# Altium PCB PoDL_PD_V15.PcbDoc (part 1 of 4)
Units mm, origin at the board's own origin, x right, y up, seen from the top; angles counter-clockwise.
Board outline 145 x 75 mm, 4 copper layers (Top Layer, Signal Layer 2, Signal Layer 3, Bottom Layer), stack 1.586 mm thick; 346 components, 228 nets, 1035 pads, 619 vias.
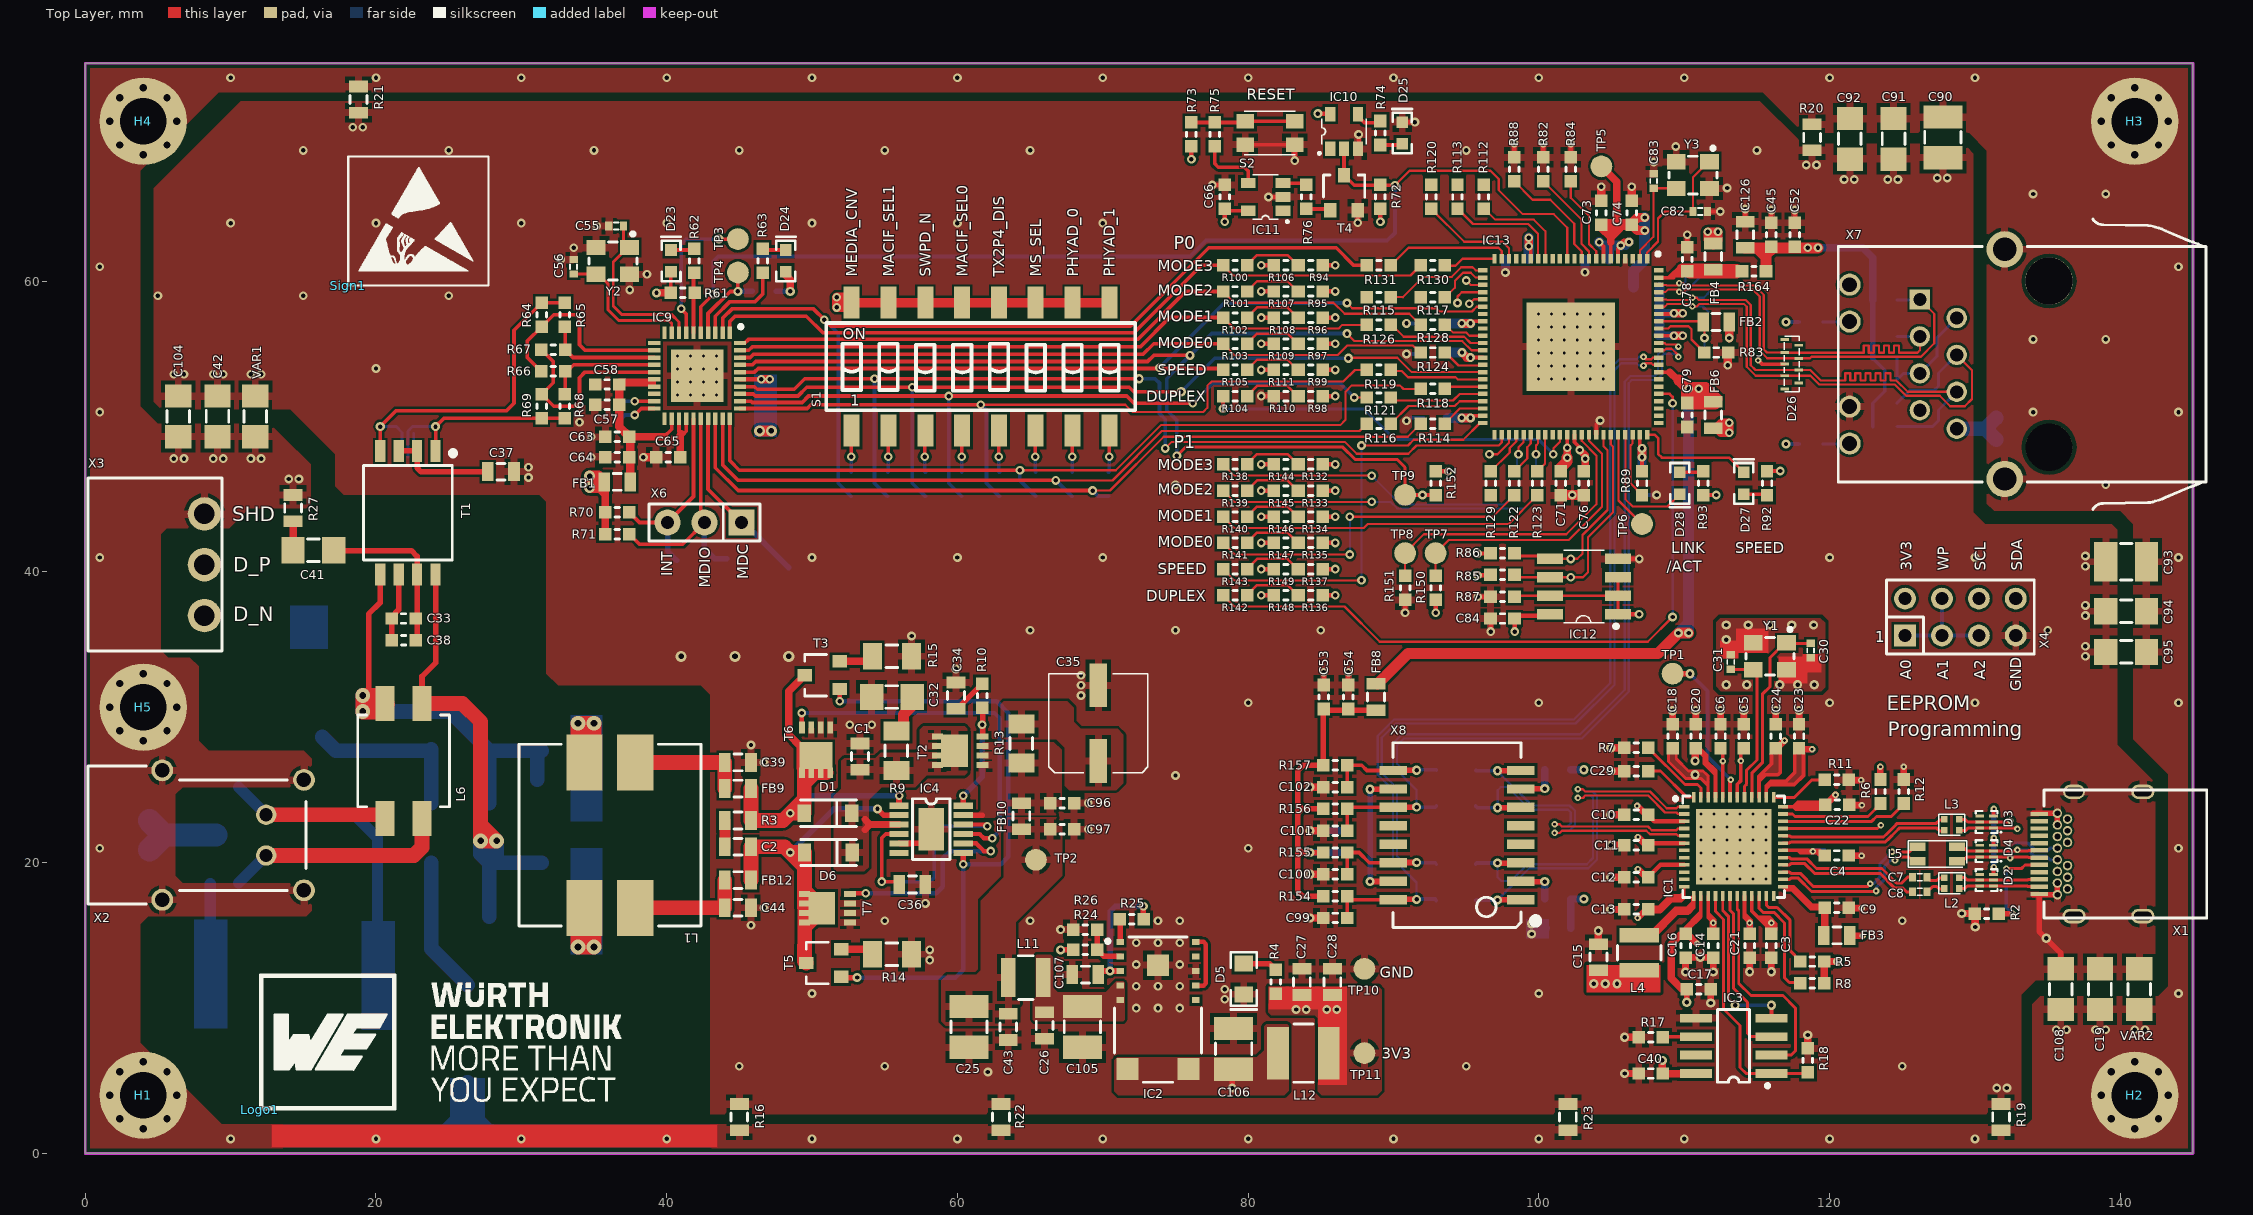
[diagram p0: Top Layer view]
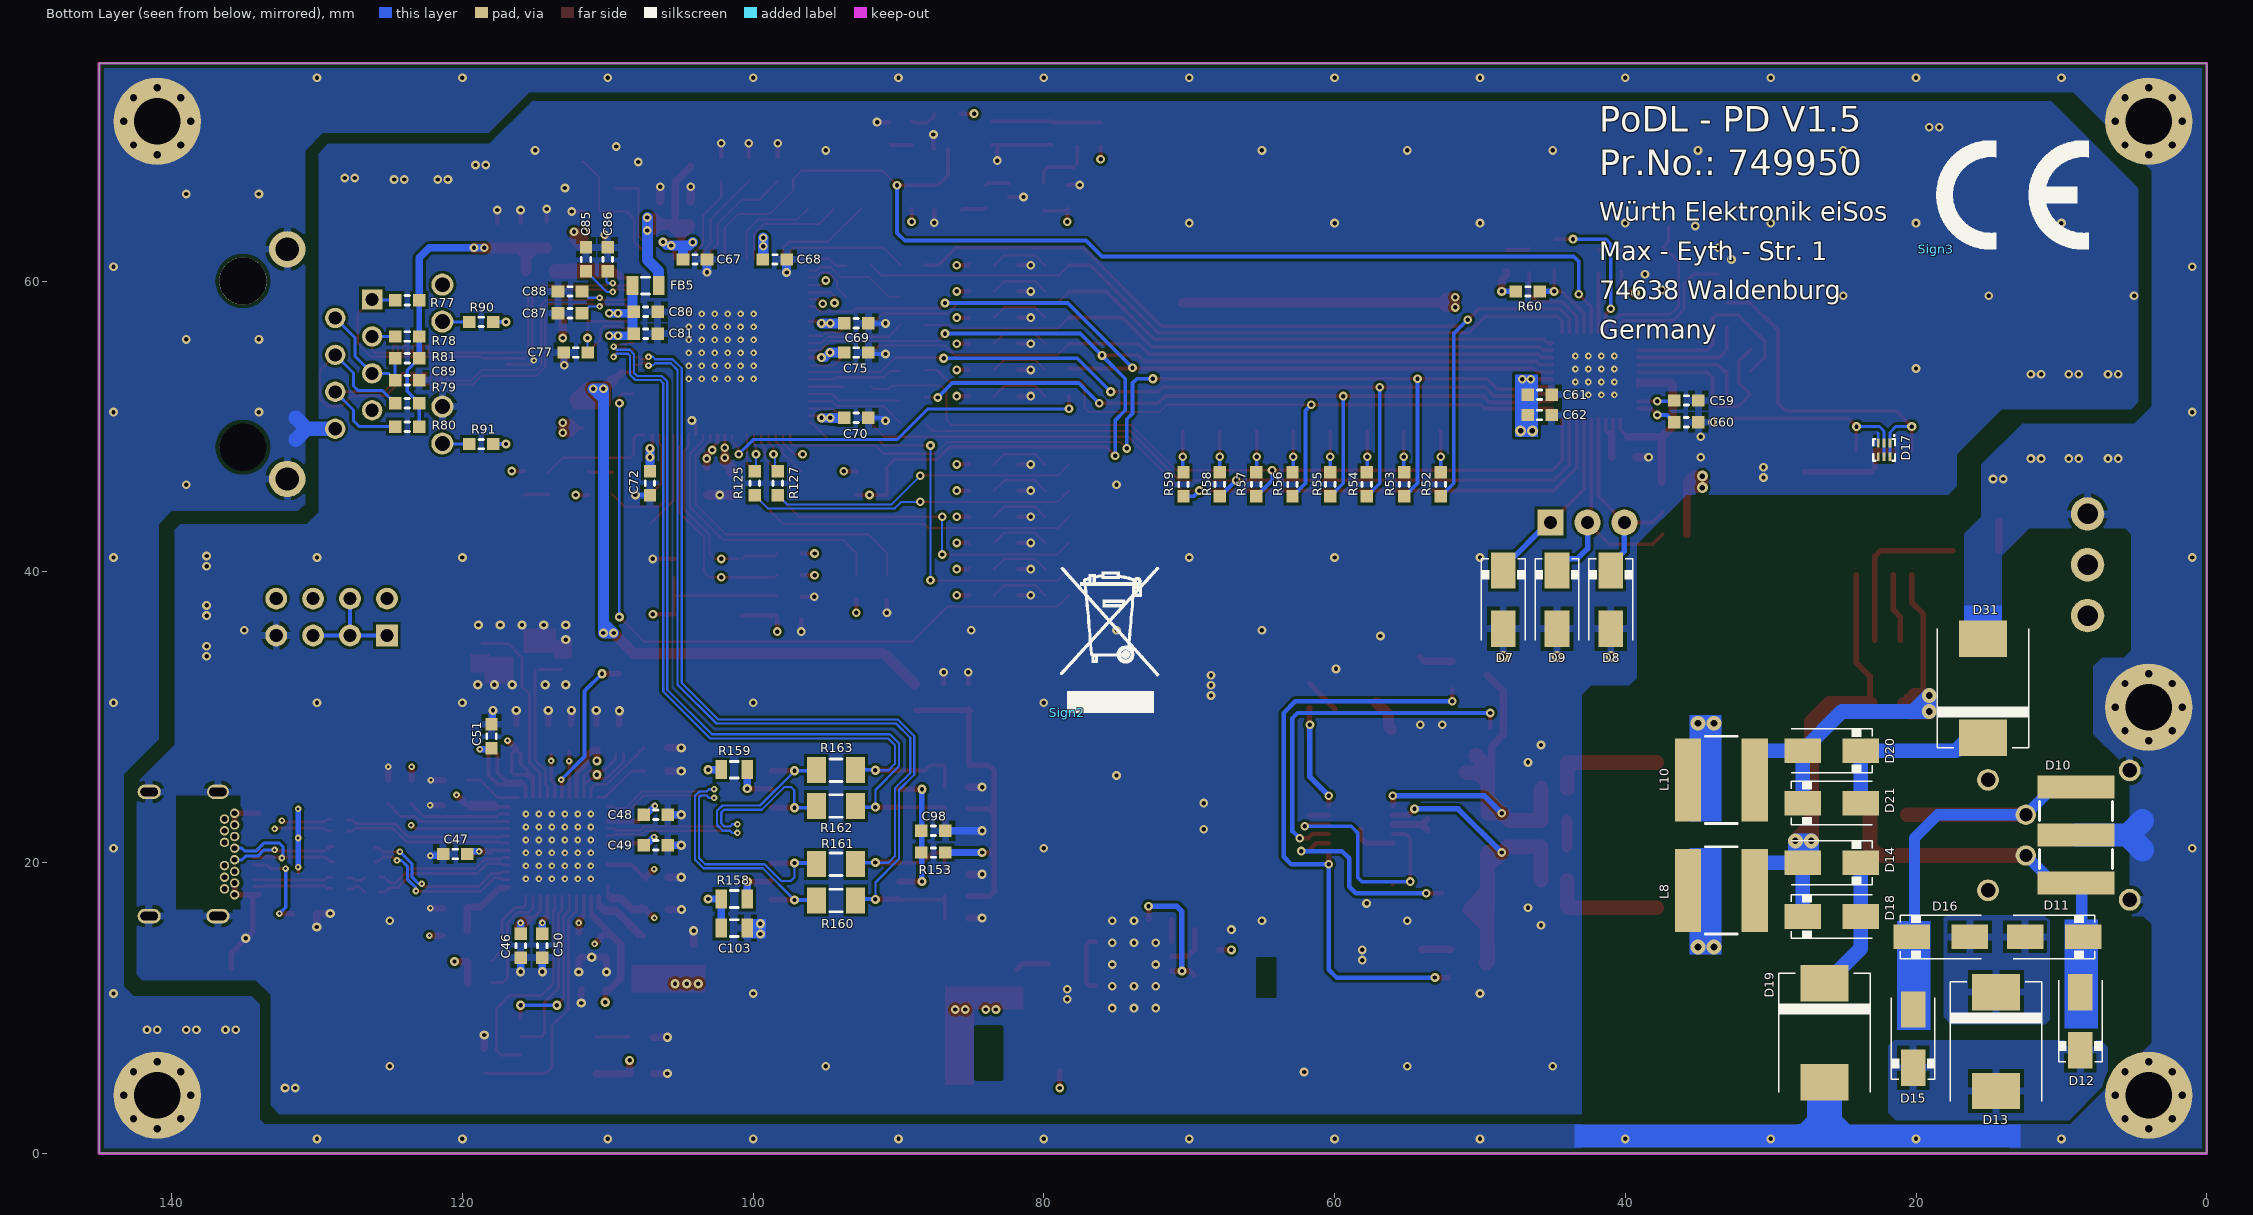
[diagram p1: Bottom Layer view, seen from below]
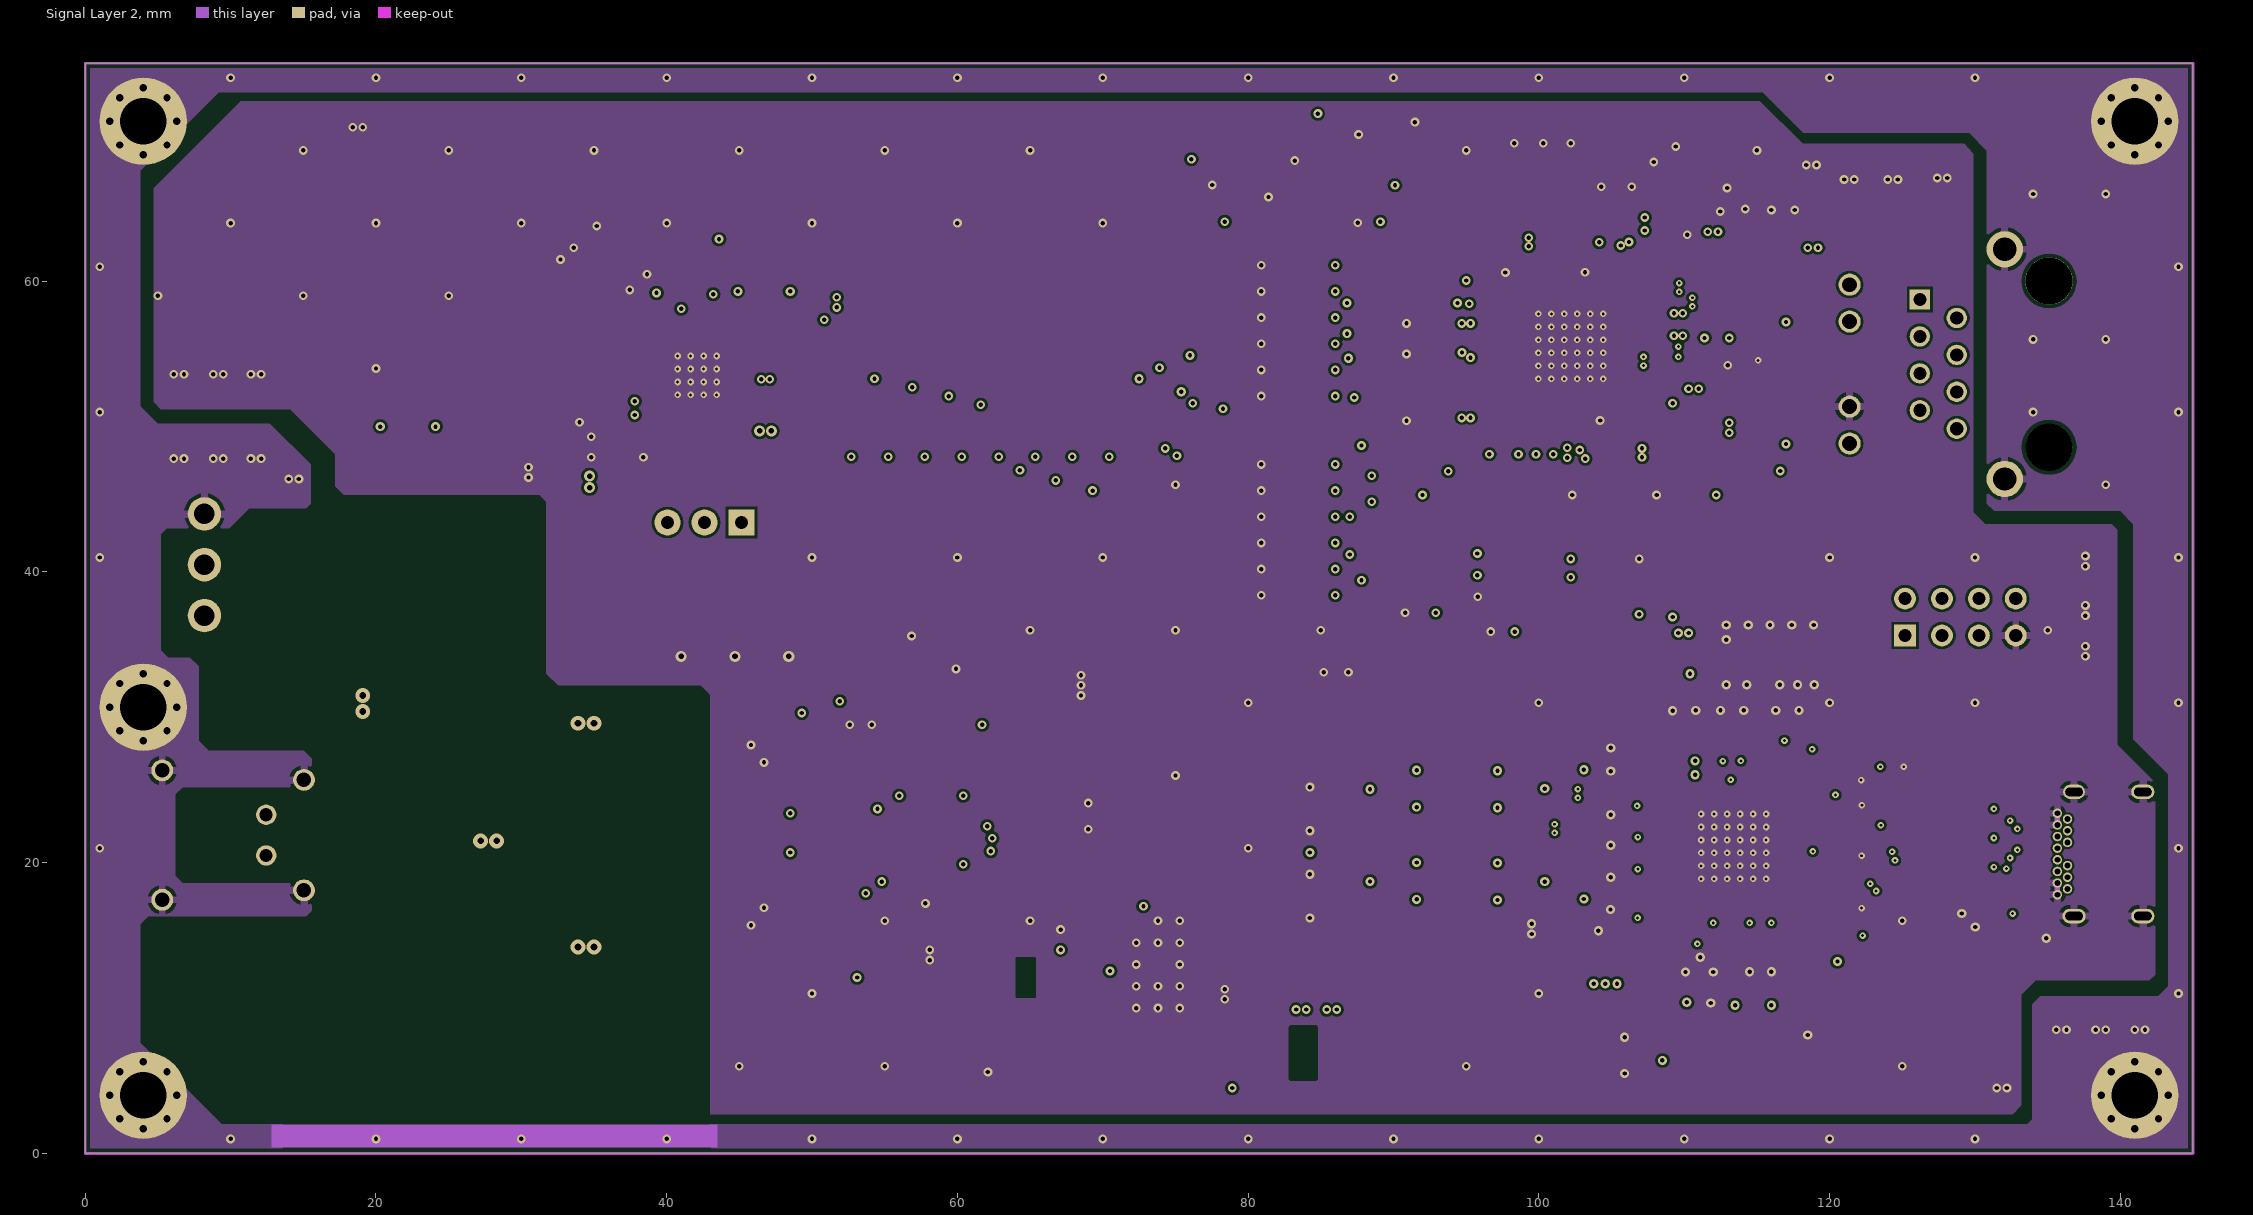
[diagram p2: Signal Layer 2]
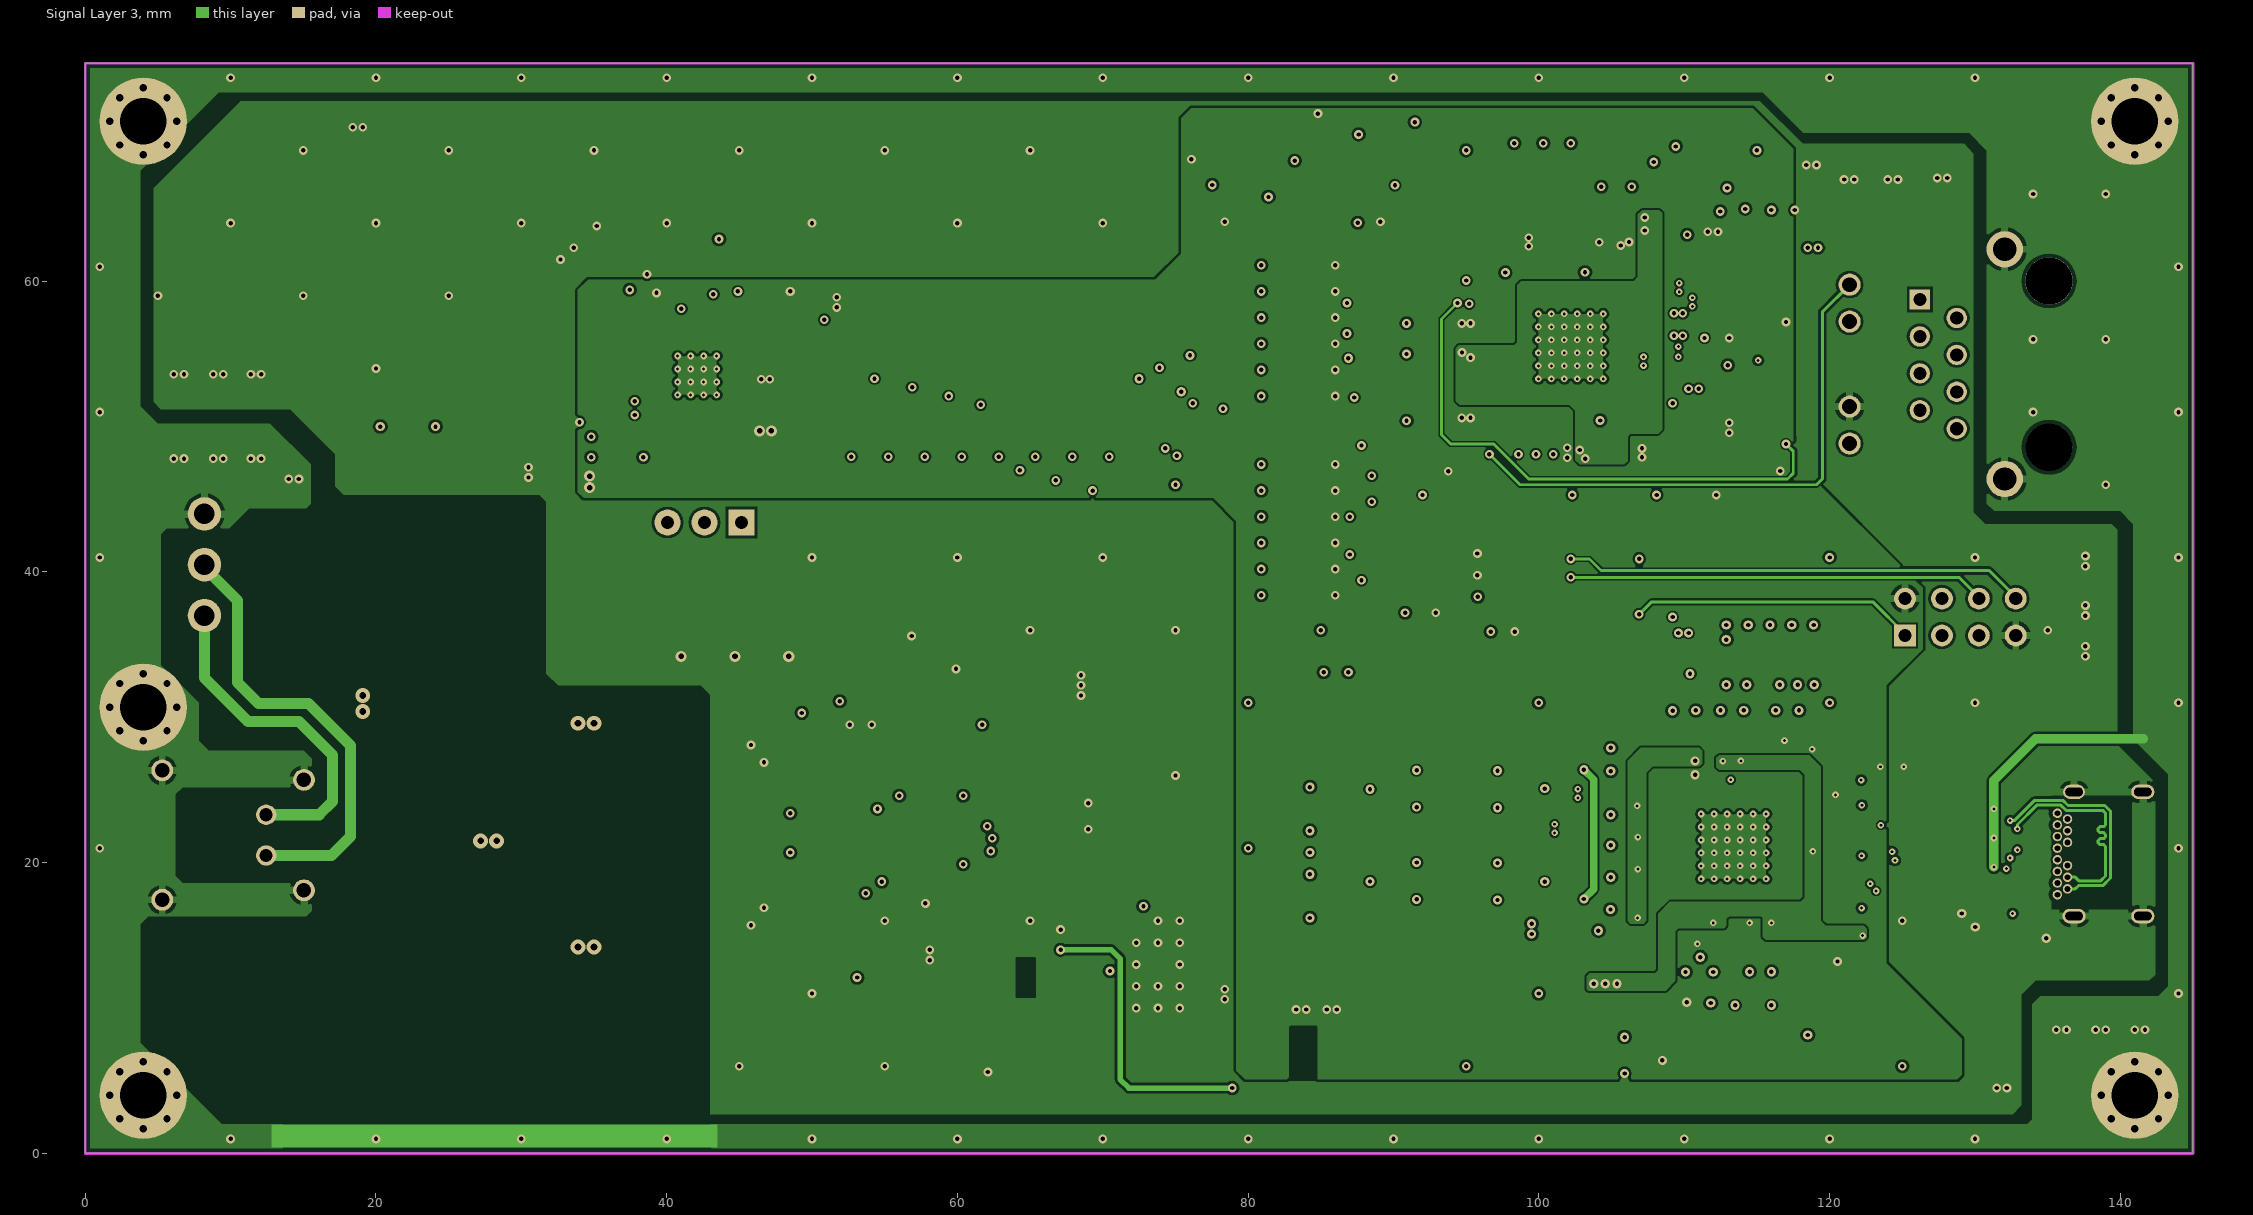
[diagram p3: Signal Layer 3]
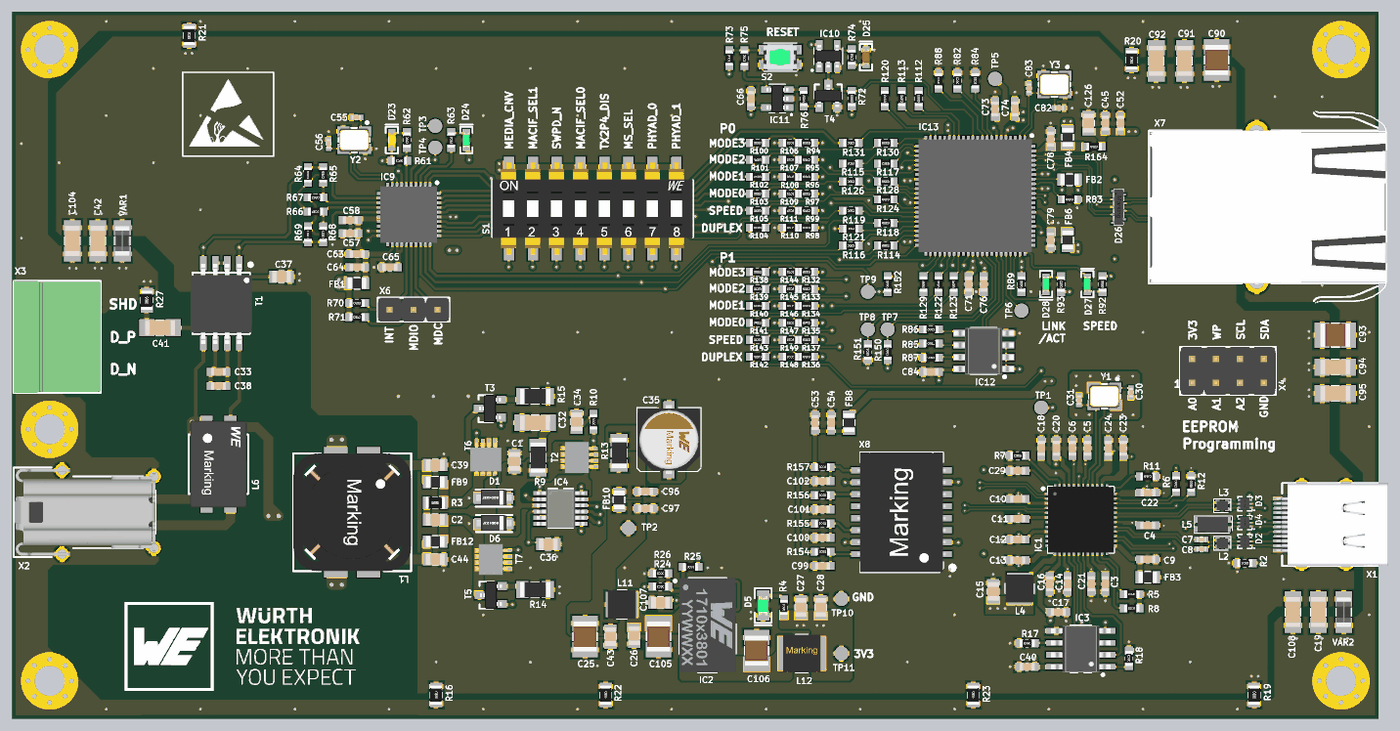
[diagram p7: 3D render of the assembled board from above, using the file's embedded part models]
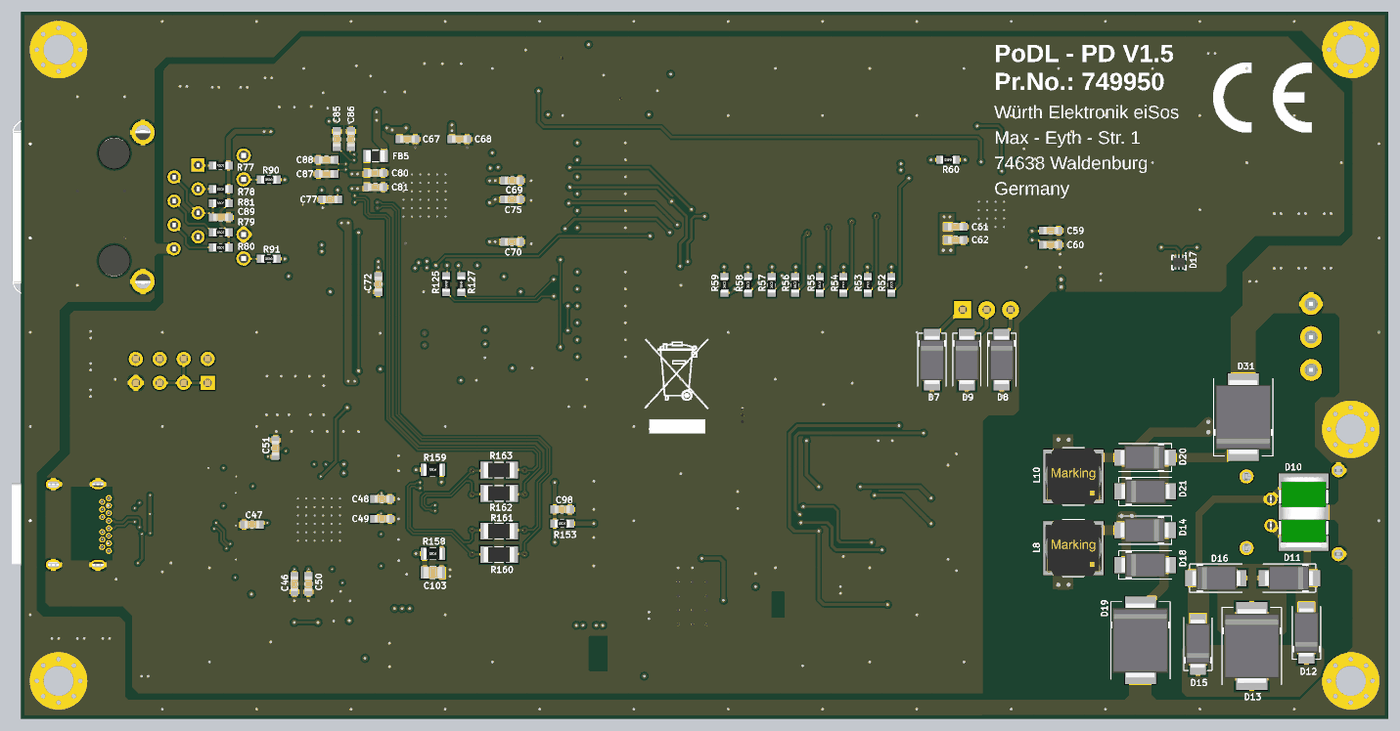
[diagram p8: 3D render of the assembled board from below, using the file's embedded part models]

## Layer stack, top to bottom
Top Solder: solder mask 0.01, Solder Resist, Dk 3.8
Top Layer: signal copper 0.035
Dielectric 1: prepreg 0.2104, 7628, Dk 4.6
Signal Layer 2: signal copper 0.0152
Dielectric 3: core 1.065, Core-009, Dk 4.6
Signal Layer 3: signal copper 0.0152
Dielectric 2: prepreg 0.2104, PP-006, Dk 4.6
Bottom Layer: signal copper 0.035
Bottom Solder: solder mask 0.01, Solder Resist, Dk 3.8

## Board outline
0,0 0,75 145,75 145,0

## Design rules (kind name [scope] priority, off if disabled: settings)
Clearance USB_to_SHIELD [InDifferentialPairClass('DiffPairs_USB') vs InNet('SHIELD')] p1: gap=0.152 ignorepadtopadclearanceinfootprint=FALSE
Clearance USB-C_Pad [InPadClass('USB-C')] p2: gap=0.127 ignorepadtopadclearanceinfootprint=FALSE
Clearance GND [InNet('GND')] p3: gap=0.178 ignorepadtopadclearanceinfootprint=FALSE
Clearance SHIELD_GND [InNet('SHIELD') vs InNet('GND')] p4: gap=0.483 ignorepadtopadclearanceinfootprint=FALSE
Clearance SHIELD_ALL [InNet('SHIELD')] p5: gap=0.254 ignorepadtopadclearanceinfootprint=FALSE
Clearance Keepout [OnLayer('Keep-Out Layer')] p6: gap=0.381 ignorepadtopadclearanceinfootprint=FALSE
Clearance [All] p7: gap=0.127 ignorepadtopadclearanceinfootprint=FALSE
ComponentClearance USB_Decoupling [InComponentClass('USB-Decoupling') vs InComponentClass('USB-Decoupling')] p1: gap=0 collisioncheckmode=3 verticalgap=0 showdistances=FALSE
ComponentClearance [All] p2: gap=0.254 collisioncheckmode=3 verticalgap=0.254 showdistances=FALSE
DiffPairsRouting DiffPairs_DADA_IN [InDifferentialPairClass('DiffPairs_DATA_IN')] p1: maxlimit=0.203 minlimit=0.203 mostfreqgap=0.203 toplayer_minwidth=0.254 toplayer_maxwidth=1.016 toplayer_prefwidth=0.254 midlayer1_minwidth=0.254 midlayer1_maxwidth=0.762 midlayer1_prefwidth=0.254 midlayer2_minwidth=0.254 midlayer2_maxwidth=0.762 midlayer2_prefwidth=0.254 bottomlayer_minwidth=0.254 bottomlayer_maxwidth=1.016 bottomlayer_prefwidth=0.254 maxuncoupledlength=12.7
DiffPairsRouting DiffPairs_USB [InDifferentialPairClass('DiffPairs_USB')] p2: maxlimit=0.254 minlimit=0.127 mostfreqgap=0.254 toplayer_maxgap=0.127 toplayer_prefgap=0.127 toplayer_minwidth=0.206 toplayer_maxwidth=0.206 toplayer_prefwidth=0.206 midlayer1_maxgap=0.127 midlayer1_prefgap=0.127 midlayer1_minwidth=0.206 midlayer1_maxwidth=0.206 midlayer1_prefwidth=0.206 midlayer2_mingap=0.254 midlayer2_minwidth=0.381 midlayer2_maxwidth=0.381 midlayer2_prefwidth=0.381 bottomlayer_maxgap=0.127 bottomlayer_prefgap=0.127 bottomlayer_minwidth=0.206 bottomlayer_maxwidth=0.206 bottomlayer_prefwidth=0.206 maxuncoupledlength=12.7
DiffPairsRouting DiffPairs_ETH [InDifferentialPairClass('DiffPairs_ETH')] p3: maxlimit=0.254 minlimit=0.127 mostfreqgap=0.254 toplayer_maxgap=0.127 toplayer_prefgap=0.127 toplayer_minwidth=0.154 toplayer_maxwidth=0.254 toplayer_prefwidth=0.154 midlayer1_maxgap=0.127 midlayer1_prefgap=0.127 midlayer1_minwidth=0.154 midlayer1_maxwidth=0.254 midlayer1_prefwidth=0.154 midlayer2_mingap=0.254 midlayer2_minwidth=0.381 midlayer2_maxwidth=0.381 midlayer2_prefwidth=0.381 bottomlayer_maxgap=0.127 bottomlayer_prefgap=0.127 bottomlayer_minwidth=0.154 bottomlayer_maxwidth=0.254 bottomlayer_prefwidth=0.154 maxuncoupledlength=12.7
HoleSize [All] p1: absolutevalues=TRUE maxlimit=5 minlimit=0.025 maxpercent=80.000 minpercent=20.000
MinimumSolderMaskSliver [All] p1 off: minsoldermaskwidth=0.254
NetAntennae [All] p1 off: netantennaetolerance=0
PlaneConnect [All] p1: pad.planeconnectstyle=Relief pad.reliefexpansion=0.508 pad.reliefentries=4 pad.reliefconductorwidth=0.381 pad.reliefairgap=0.203 via.planeconnectstyle=Direct via.reliefexpansion=0.508 via.reliefentries=4 via.reliefconductorwidth=0.254 via.reliefairgap=0.254
PolygonConnect Polygon_NetC106_1 [InNet('NetC106_1')] p1: connectstyle=Direct reliefconductorwidth=0.254 reliefentries=4 polygonreliefangle="90 Angle" airgapwidth=0.254
PolygonConnect Polygon_NetC26_1 [InNet('NetC26_1')] p2: connectstyle=Direct reliefconductorwidth=0.254 reliefentries=4 polygonreliefangle="90 Angle" airgapwidth=0.254
PolygonConnect PolygonTransformer [InNetClass('Transformer')] p3: connectstyle=Direct reliefconductorwidth=0.254 reliefentries=4 polygonreliefangle="90 Angle" airgapwidth=0.254
PolygonConnect "Polygon_SHIELD_USB_Fix hole" [InPadClass('Fix_Hole') vs InNet('SHIELD_USB')] p4: thpad.connectstyle=Direct thpad.reliefconductorwidth=0.254 thpad.reliefentries=4 thpad.polygonreliefangle="90 Angle" thpad.airgapwidth=0.254 smdpad.connectstyle=Relief smdpad.reliefconductorwidth=0.508 smdpad.reliefentries=4 smdpad.polygonreliefangle="90 Angle" smdpad.airgapwidth=0.254 via.connectstyle=Direct via.reliefconductorwidth=0.254 via.reliefentries=4 via.polygonreliefangle="90 Angle" via.airgapwidth=0.254
PolygonConnect Poly_GND_OSC [InNamedPolygon('GND_OSC') vs InNet('GND')] p5: connectstyle=Direct reliefconductorwidth=0.254 reliefentries=4 polygonreliefangle="90 Angle" airgapwidth=0.254
PolygonConnect "Poly_SHIELD_Fix hole" [InPadClass('Fix_Hole') vs InNet('SHIELD')] p6: thpad.connectstyle=Direct thpad.reliefconductorwidth=0.254 thpad.reliefentries=4 thpad.polygonreliefangle="90 Angle" thpad.airgapwidth=0.254 smdpad.connectstyle=Relief smdpad.reliefconductorwidth=0.508 smdpad.reliefentries=4 smdpad.polygonreliefangle="90 Angle" smdpad.airgapwidth=0.254 via.connectstyle=Direct via.reliefconductorwidth=0.254 via.reliefentries=4 via.polygonreliefangle="90 Angle" via.airgapwidth=0.254
PolygonConnect Poly_SHIELD [All vs InNet('SHIELD')] p7: thpad.connectstyle=Relief thpad.reliefconductorwidth=0.508 thpad.reliefentries=4 thpad.polygonreliefangle="90 Angle" thpad.airgapwidth=0.254 smdpad.connectstyle=Relief smdpad.reliefconductorwidth=0.508 smdpad.reliefentries=4 smdpad.polygonreliefangle="90 Angle" smdpad.airgapwidth=0.254 via.connectstyle=Direct via.reliefconductorwidth=0.254 via.reliefentries=4 via.polygonreliefangle="90 Angle" via.airgapwidth=0.254
PolygonConnect [All] p8: thpad.connectstyle=Relief thpad.reliefconductorwidth=0.508 thpad.reliefentries=4 thpad.polygonreliefangle="90 Angle" thpad.airgapwidth=0.254 smdpad.connectstyle=Relief smdpad.reliefconductorwidth=0.508 smdpad.reliefentries=4 smdpad.polygonreliefangle="90 Angle" smdpad.airgapwidth=0.254 via.connectstyle=Direct via.reliefconductorwidth=0.254 via.reliefentries=4 via.polygonreliefangle="90 Angle" via.airgapwidth=0.254
RoutingVias [All] p1: holewidth=0.2 width=0.5 viastyle="Through Hole" minholewidth=0.2 minwidth=0.45 maxholewidth=0.711 maxwidth=1.27
SilkToSilkClearance [All] p1 off: silktosilkclearance=0.254
SilkToSolderMaskClearance [IsPad] p1 off: minsilkscreentomaskgap=0.254 clearancetoexposedcopper=TRUE
SolderMaskExpansion [All] p1: expansion=0.102
Width [All] p1: maxlimit=2.54 minlimit=0.127 preferedwidth=0.254 minimp=50.000000 maximp=50.000000 favimp=50.000000
22 further rules are at their usual default settings.

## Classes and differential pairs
differential pair class DiffPairs_DATA_IN: POWER/DATA
differential pair class DiffPairs_ETH: RXA TR0 TR1 TXA
differential pair class DiffPairs_USB: D USB2D USB2D1 USB3RX USB3RX1 USB3TX USB3TX1
component class USB-Decoupling: L6
component class U_04-LAN_to_USB-C: C3 C4 C5 C6 C7 C8 C9 C10 C11 C12 C13 C14 C15 C16 C17 C18 C19 C20 C21 C22 C23 C24 C29 C30 C31 C40 C46 C47 C48 C49 C50 C51 C53 C54 C98 C99 C100 C101 C102 C103 C108 D2 D3 D4 FB3 FB8 IC1 IC3 L2 L3 L4 L5 R2 R5 R6 R7 R8 R11 R12 R17 R18 R153 R154 R155 R156 R157 R158 R159 R160 R161 R162 R163 TP1 VAR2 X1 X8 Y1
component class U_03-LAN_3-Ports_Switch: C45 C52 C66 C67 C68 C69 C70 C71 C72 C73 C74 C75 C76 C77 C78 C79 C80 C81 C82 C83 C84 C85 C86 C87 C88 C89 C90 C91 C92 C93 C94 C95 C126 D25 D26 D27 D28 FB2 FB4 FB5 FB6 IC10 IC11 IC12 IC13 R72 R73 R74 R75 R76 R77 R78 R79 R80 R81 R82 R83 R84 R85 R86 R87 R88 R89 R90 R91 R92 R93 R94 R95 R96 R97 R98 R99 R100 R101 R102 R103 R104 R105 R106 R107 R108 R109 R110 R111 R112 R113 R114 R115 R116 R117 R118 R119 R120 R121 R122 R123 R124 R125 R126 R127 R128 R129 R130 R131 R132 R133 R134 R135 R136 R137 R138 R139 R140 R141 R142 R143 R144 R145 R146 R147 R148 R149 R150 R151 R152 R164 S2 T4 TP5 TP6 TP7 TP8 TP9 X4 X7 Y3
component class U_02-10BASE-T1L_PHY: C55 C56 C57 C58 C59 C60 C61 C62 C63 C64 C65 D7 D8 D9 D23 D24 FB1 IC9 R52 R53 R54 R55 R56 R57 R58 R59 R60 R61 R62 R63 R64 R65 R66 R67 R68 R69 R70 R71 S1 TP3 TP4 X6 Y2
component class U_01-PD_Power_MCU: C1 C2 C25 C26 C27 C28 C32 C33 C34 C35 C36 C37 C38 C39 C41 C42 C43 C44 C96 C97 C104 C105 C106 C107 D1 D5 D6 D10 D11 D12 D13 D14 D15 D16 D17 D18 D19 D20 D21 D31 FB9 FB10 FB12 H1 H2 H3 H4 H5 IC2 IC4 L1 L6 L8 L10 L11 L12 Logo1 R3 R4 R9 R10 R13 R14 R15 R16 R19 R20 R21 R22 R23 R24 R25 R26 R27 Sign1 Sign2 Sign3 T1 T2 T3 T5 T6 T7 TP2 TP10 TP11 VAR1 X2 X3
pad class USB-C: X1-B1 X1-B2 X1-B3 X1-B4 X1-B5 X1-B6 X1-B7 X1-B8 X1-B9 X1-B10 X1-B11 X1-B12
pad class Fix_Hole: H1-0 H2-0 H3-0 H4-0 H5-0
differential pair TXB: +TXB_P -TXB_N
differential pair RXB: +RXB_P -RXB_N
differential pair USB3TX: +USB3TX_P -USB3TX_N
differential pair USB3TX1: +USB3TX1_P -USB3TX1_N
differential pair USB3RX: +USB3RX_P -USB3RX_N
differential pair USB3RX1: +USB3RX1_P -USB3RX1_N
differential pair USB2D: +USB2D_P -USB2D_N
differential pair USB2D1: +USB2D1_P -USB2D1_N
differential pair TXA: +TXA_P -TXA_N
differential pair TR1: +TR1_P -TR1_N
differential pair TR0: +TR0_P -TR0_N
differential pair RXA: +RXA_P -RXA_N
differential pair POWER/DATA: +POWER/DATA_P -POWER/DATA_N
differential pair D: +D_P -D_N

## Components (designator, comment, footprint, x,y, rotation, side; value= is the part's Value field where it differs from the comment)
C1 "885012207126" CC2012-0805 53.3,27.3 r90 top value=47nF
C2 "885012207126" CC2012-0805 44.9,21.1 r0 top value=47nF
C3 "885012206071" CC1608-0603 116,14.3 r270 top value=100nF
C4 "885012206071" CC1608-0603 120.5,20.5 r0 top value=100nF
C5 "885012206071" CC1608-0603 114.1,28.7 r90 top value=100nF
C6 "885012206071" CC1608-0603 112.5,28.7 r90 top value=100nF
C7 "885012105018" CC1005-0402 126.2,19 r180 top value=100nF
C8 "885012105018" CC1005-0402 126.2,18 r180 top value=100nF
C9 "885012206052" CC1608-0603 120.5,16.9 r0 top value=1uF
C10 "885012206071" CC1608-0603 106.7,23.3 r180 top value=100nF
C11 "885012206071" CC1608-0603 106.7,21.2 r180 top value=100nF
C12 "885012206071" CC1608-0603 106.7,19 r180 top value=100nF
C13 "885012206071" CC1608-0603 106.7,16.8 r180 top value=100nF
C14 "885012206071" CC1608-0603 112,14.3 r270 top value=100nF
C15 "885012107005" CC2012-0805 104.1,13.5 r270 top value=22uF
C16 "885012206071" CC1608-0603 110.1,14.3 r270 top value=100nF
C17 "885012106006" CC1608-0603 111,11.3 r180 top value=10uF
C18 "885012206052" CC1608-0603 109.2,28.7 r90 top value=1uF
C19 "885012208112" CC3216-1206 138.6,11.3 r270 top value=10nF
C20 "885012206052" CC1608-0603 110.8,28.7 r90 top value=1uF
C21 "885012206071" CC1608-0603 114.5,14.3 r270 top value=100nF
C22 "885012206071" CC1608-0603 120.525,23.975 r0 top value=100nF
C23 "885012206071" CC1608-0603 117.9,28.7 r90 top value=100nF
C24 "885012206071" CC1608-0603 116.3,28.7 r90 top value=100nF
C25 "885012209073" CC3225-1210 60.8,8.7 r270 top value=10uF
C26 "885012207098" CC2012-0805 66,8.8 r270 top value=100nF
C27 "885012207026" CC2012-0805 83.7,11.8 r90 top value=10uF
C28 "885012207026" CC2012-0805 85.8,11.8 r90 top value=10uF
C29 "885012206052" CC1608-0603 106.7,26.3 r180 top value=1uF
C30 "885012005056" CC1005-0402 118.7,34.6 r90 top value=15pF
C31 "885012005056" CC1005-0402 113.2,33.8 r270 top value=15pF
C32 "885012208119" CC3216-1206 55.5,31.4 r180 top value=150nF
C33 "885012206120" CC1608-0603 21.9,36.8 r0 top value=100nF
C34 "885012207124" CC2012-0805 59.9,31.5 r90 top value=22nF
C35 "865080645012" "SMT 6.3mmx7.7mm - WE" 69.7,29.6 r180 top value=47uF
C36 "885012207001" CC2012-0805 56.9,18.5 r0 top value=2.2uF
C37 "885012207128" CC2012-0805 28.6,46.9 r0 top value=100nF
C38 "885012206120" CC1608-0603 21.9,35.3 r0 top value=100nF
C39 "885342207005" CC2012-0805 44.9,26.9 r0 top value=10nF
C40 "885012206071" CC1608-0603 107.7,5.5 r180 top value=100nF
C41 "885342208021" CC3216-1206 15.7,41.5 r180 top value=10nF
C42 "885012208112" CC3216-1206 9.1,50.7 r90 top value=10nF
C43 "885012207098" CC2012-0805 63.5,8.7 r270 top value=100nF
C44 "885342207005" CC2012-0805 44.9,16.9 r0 top value=10nF
C45 "885012206093" CC1608-0603 116,63.2 r90 top value=47nF
C46 "885012206071" CC1608-0603 116,14.3 r270 bottom value=100nF
C47 "885012206071" CC1608-0603 120.5,20.6 r0 bottom value=100nF
C48 "885012206071" CC1608-0603 106.7,23.3 r180 bottom value=100nF
C49 "885012206071" CC1608-0603 106.7,21.2 r180 bottom value=100nF
C50 "885012206071" CC1608-0603 114.5,14.3 r270 bottom value=100nF
C51 "885012206071" CC1608-0603 118,28.7 r90 bottom value=100nF
C52 "885012206093" CC1608-0603 117.6,63.2 r90 top value=47nF
C53 "885012206093" CC1608-0603 85.2,31.4 r90 top value=47nF
C54 "885012206093" CC1608-0603 86.9,31.4 r90 top value=47nF
C55 "885012005056" CC1005-0402 36.525,63.8 r0 top value=15pF
C56 "885012005056" CC1005-0402 33.6,61 r270 top value=15pF
C57 "885012206071" CC1608-0603 35.9,51.5 r180 top value=100nF
C58 "885012206040" CC1608-0603 35.9,52.9 r180 top value=10nF
C59 "885012206071" CC1608-0603 35.8,51.8 r180 bottom value=100nF
C60 "885012206052" CC1608-0603 35.8,50.3 r180 bottom value=1uF
C61 "885012206040" CC1608-0603 45.9,52.2 r180 bottom value=10nF
C62 "885012206071" CC1608-0603 45.9,50.8 r180 bottom value=100nF
C63 "885012206071" CC1608-0603 36.6,49.3 r180 top value=100nF
C64 "885012206040" CC1608-0603 36.6,47.9 r180 top value=10nF
C65 "885012206051" CC1608-0603 40.1,47.9 r180 top value=680nF
C66 "885012206071" CC1608-0603 78.4,65.8 r270 top value=100nF
C67 "885012206071" CC1608-0603 104,61.5 r180 bottom value=100nF
C68 "885012206071" CC1608-0603 98.5,61.5 r180 bottom value=100nF
C69 "885012206071" CC1608-0603 92.9,57.1 r180 bottom value=100nF
C70 "885012206071" CC1608-0603 92.9,50.6 r180 bottom value=100nF
C71 "885012206071" CC1608-0603 101.5,46.1 r270 top value=100nF
C72 "885012206071" CC1608-0603 107.1,46.1 r270 bottom value=100nF
C73 "885012206026" CC1608-0603 104.3,64.7 r270 top value=1uF
C74 "885012206081" CC1608-0603 106.4,64.7 r90 top value=470pF
C75 "885012206071" CC1608-0603 92.9,55.1 r180 bottom value=100nF
C76 "885012206071" CC1608-0603 103.1,46.1 r270 top value=100nF
C77 "885012206071" CC1608-0603 112.2,55.1 r0 bottom value=100nF
C78 "885012206071" CC1608-0603 110.2,61.5 r90 top value=100nF
C79 "885012206071" CC1608-0603 110.2,50.8 r270 top value=100nF
C80 "885012206071" CC1608-0603 107.4,57.9 r180 bottom value=100nF
C81 "885012206071" CC1608-0603 107.4,56.4 r180 bottom value=100nF
C82 "885012005056" CC1005-0402 111.1,64.8 r180 top value=15pF
C83 "885012005056" CC1005-0402 107.9,66.9 r270 top value=15pF
C84 "885012206071" CC1608-0603 97.5,36.8 r0 top value=100nF
C85 "885012006051" CC1608-0603 111.5,61.5 r90 bottom value=10pF
C86 "885012006051" CC1608-0603 110,61.5 r90 bottom value=10pF
C87 "885012006051" CC1608-0603 112.6,57.8 r0 bottom value=10pF
C88 "885012006051" CC1608-0603 112.6,59.3 r0 bottom value=10pF
C89 "885012206091" CC1608-0603 123.8,53.2 r180 bottom value=22nF
C90 "" CC3225-1210 127.8,69.9 r270 top value=TBE
C91 "" CC3216-1206 124.4,69.8 r270 top value=TBE
C92 "" CC3216-1206 121.4,69.8 r270 top value=TBE
C93 "" CC3225-1210 140.4,40.7 r180 top value=TBE
C94 "" CC3216-1206 140.4,37.3 r180 top value=TBE
C95 "" CC3216-1206 140.4,34.5 r180 top value=TBE
C96 "885012206120" CC1608-0603 67.2,24.1 r0 top value=100nF
C97 "885012206120" CC1608-0603 67.2,22.3 r0 top value=100nF
C98 "885012206091" CC1608-0603 87.6,22.2 r180 bottom value=22nF
C99 "885012006051" CC1608-0603 86,16.2 r180 top value=10pF
C100 "885012006051" CC1608-0603 86,19.2 r180 top value=10pF
C101 "885012006051" CC1608-0603 86,22.2 r180 top value=10pF
C102 "885012006051" CC1608-0603 86,25.2 r180 top value=10pF
C103 "885012207116" CC2012-0805 101.3,15.5 r180 bottom value=1nF
C104 "885012208112" CC3216-1206 6.4,50.7 r90 top value=10nF
C105 "885012209048" CC3225-1210 68.6,8.7 r270 top value=4.7uF
C106 "885012209048" CC3225-1210 79,7.2 r90 top value=4.7uF
C107 "885012207051" CC2012-0805 68.8,12.3 r180 top value=1uF
C108 "885012208112" CC3216-1206 135.9,11.3 r270 top value=10nF
C126 "885012007063" CC2012-0805 114.2,63.2 r90 top value=1nF
D1 "PMEG10020AELRX" SOD-123FL 51.1,23.4 r0 top
D2 "824012823" "DFN1210-6L 1.2X1.0" 130.8,18.8 r90 top
D3 "824012823" "DFN1210-6L 1.2X1.0" 130.8,22.8 r90 top
D4 "824012823" "DFN1210-6L 1.2X1.0" 130.8,20.8 r90 top
D5 "150080VS75000" "LED2012 (0805) - Green" 79.7,12 r90 top value=Green
D6 "PMEG10020AELRX" SOD-123FL 51.125,20.7 r0 top
D7 "824500500" SMA/DO-214AC 48.4,38.1 r90 bottom
D8 "824500500" SMA/DO-214AC 41,38.1 r90 bottom
D9 "824500500" SMA/DO-214AC 44.7,38.1 r90 bottom
D10 "2038-15-SM-RPLF" 2038-xx 9,21.9 r90 bottom value=150V
D11 "S1B-13-F" SMA/DO-214AC 10.5,14.9 r180 bottom
D12 "S1B-13-F" SMA/DO-214AC 8.7,9.1 r270 bottom
D13 "SMCJ36CA" SMC/DO-214AB 14.5,7.7 r90 bottom
D14 "S1D-13-F" SMA/DO-214AC 25.8,20 r180 bottom
D15 "S1B-13-F" SMA/DO-214AC 20.2,7.9 r270 bottom
D16 "S1B-13-F" SMA/DO-214AC 18.3,14.9 r0 bottom
D17 "824012823" "DFN1210-6L 1.2X1.0" 22.2,48.4 r0 bottom
D18 "S1D-13-F" SMA/DO-214AC 25.8,16.3 r0 bottom
D19 "824541361" SMC/DO-214AB 26.3,8.3 r90 bottom
D20 "S1D-13-F" SMA/DO-214AC 25.8,27.7 r180 bottom
D21 "S1D-13-F" SMA/DO-214AC 25.8,24.1 r0 bottom
D23 "LTST-C190KSKT" "LED1608 (0603) - YELLOW" 40.3,61.4 r270 top value=Yellow
D24 "150060VS75020" "LED1608 (0603) - Green" 48.2,61.4 r270 top value=Green
D25 "150060SS75020" "LED1608 (0603) - Red" 90.6,70.2 r270 top value=Red
D26 "824014885" WE-TVS_824014885 117.4,54.3 r270 top
D27 "150060VS75020" "LED1608 (0603) - Green" 114.1,46.1 r270 top value=Green
D28 "150060VS75020" "LED1608 (0603) - Green" 109.7,46.1 r90 top value=Green
D31 "824541361" SMC/DO-214AB 15.4,32 r270 bottom
FB1 "742792031" CF2012-0805 36.6,46.2 r0 top value=300R@100MHz
FB2 "742792031" CF2012-0805 112.2,57.2 r180 top value=300R@100MHz
FB3 "742792031" CF2012-0805 120.5,15 r0 top value=300R
FB4 "742792031" CF2012-0805 112,61.7 r270 top value=300R@100MHz
FB5 "742792031" CF2012-0805 107.4,59.7 r180 bottom value=300R@100MHz
FB6 "742792031" CF2012-0805 112,50.8 r90 top value=300R@100MHz
FB8 "742792040" CF2012-0805 88.8,31.4 r90 top value=600R@100MHz
FB9 "742792031" CF2012-0805 44.9,25.1 r0 top value=300R@100MHz
FB10 "742792031" CF2012-0805 64.4,23.2 r270 top value=300R@100MHz
FB12 "742792031" CF2012-0805 44.9,18.8 r0 top value=300R@100MHz
H1 "Hole M3 with Vias" M3_VIA 4,4 r0 top
H2 "Hole M3 with Vias" M3_VIA 141,4 r0 top
H3 "Hole M3 with Vias" M3_VIA 141,71 r0 top
H4 "Hole M3 with Vias" M3_VIA 4,71 r0 top
H5 "Hole M3 with Vias" M3_VIA 4,30.7 r90 top
IC1 "LAN7800/Y9X" "QFN-48 7x7MM" 113.4,21.1 r0 top value=LAN7800
IC2 "171033801" MAGI³C-VDRM_LGA-12EP 73.8,9.9 r270 top
IC3 "93AA66C-I/SN" SO-8N 113.4,7.4 r90 top
IC4 "LTC9111RMSE#PBF" "MSOP-12 PAD" 58.2,22.3 r0 top value=LTC9111RMSE
IC9 "ADIN1100CCPZ-R7" "QFN-40 6x6MM" 42.1,53.5 r270 top value=ADIN1100CCPZ
IC10 "74LVC1G14GV,125" SOT-23-5 86.6,70.3 r0 top value=74LVC1G14GV
IC11 "TPS3125L30DBVR" SOT-23-5 81.2,65.8 r90 top value=TPS3125L30
IC12 "24FC512-I/SN" SO-8 103.1,39 r90 top value=24FC512
IC13 "LAN9355I/ML" "QFN-88 12X12MM" 102.2,55.5 r270 top value=LAN9355
L1 "744870471_(2)" "Inductor_WE-DD 1280" 36.1,21.9 r0 top value=2x470uH
L2 "7442335600" INDUCTOR_WE-CNSW-HF-0504 128.4,18.6 r180 top value="60R @ 100MHz"
L3 "7442335600" INDUCTOR_WE-CNSW-HF-0504 128.4,22.6 r180 top value="60R @ 100MHz"
L4 "74404032033" "Inductor_WE-LQS 3015" 106.9,13.8 r270 top value=3.3uH
L5 "744232090" INDUCTOR_WE-CNSW-1206 127.4,20.6 r180 top value="90R @ 100MHz"
L6 "744224" Inductor_WE-SL2 21.9,27 r270 top value=2x250uH
L8 "74404064220" "Inductor_WE-LQS 6045" 33.4,18.1 r180 bottom value=22uH
L10 "74404064220" "Inductor_WE-LQS 6045" 33.4,25.7 r180 bottom value=22uH
L11 "74404032220" "Inductor_WE-LQS 3015" 64.7,12.1 r0 top value=22uH
L12 "74404042047" Inductor_WE-LQS-4018 83.8,6.9 r0 top value=4.7uH
Logo1 "Wurth_994x400" Wurth_994x400 12,3 r0 top
R2 "RC0603FR-075K1L" CR1608-0603 130.8,16.5 r180 top value=5k1
R3 "560112120020" CR2012-0805 44.9,22.9 r180 top value=100R
R4 "560112116020" CR1608-0603 81.9,11.8 r90 top value=330R
R5 "560112116005" CR1608-0603 118.8,13.2 r180 top value=10k
R6 "560112116005" CR1608-0603 123.5,24.9 r270 top value=10k
R7 "560112116091" CR1608-0603 106.7,27.9 r180 top value=2k
R8 "RC0603FR-0710KL" CR1608-0603 118.8,11.7 r0 top value=10k
R9 "RC1206FR-0740R2L" CR3216-1206 55.8,27.7 r90 top value=40R2
R10 "560112116005" CR1608-0603 61.7,31.5 r90 top value=10k
R11 "560112116040" CR1608-0603 120.5,25.7 r0 top value=12k
R12 "560112116005" CR1608-0603 125.1,24.9 r90 top value=10k
R13 "RC1206FR-073R3L" CR3216-1206 64.4,28.2 r90 top value=3R3
R14 "RC1206FR-073R3L" CR3216-1206 55.5,13.7 r0 top value=3R3
R15 "RC1206FR-073R3L" CR3216-1206 55.5,34.2 r0 top value=3R3
R16 "RC0805JR-070RL" CR2012-0805 45,2.5 r270 top value=0R
R17 "560112116005" CR1608-0603 107.7,8 r180 top value=10k
R18 "560112116005" CR1608-0603 118.5,6.4 r90 top value=10k
R19 "RC0805JR-070RL" CR2012-0805 131.8,2.5 r270 top value=0R
R20 "RC0805JR-070RL" CR2012-0805 118.8,69.9 r90 top value=0R
R21 "RC0805JR-070RL" CR2012-0805 18.8,72.5 r90 top value=0R
R22 "RC0805JR-070RL" CR2012-0805 63,2.5 r270 top value=0R
R23 "RC0805JR-070RL" CR2012-0805 102,2.5 r270 top value=0R
R24 "RC0603FR-07402KL" CR1608-0603 68.8,14 r180 top value=402k
R25 "560112116017" CR1608-0603 72,16.1 r0 top value=5k6
R26 "RC0603FR-07137KL" CR1608-0603 68.8,15.4 r180 top value=137k
R27 "560112120020" CR2012-0805 14.3,44.4 r90 top value=100R
R52 "560112116006" CR1608-0603 52.7,46.025 r90 bottom value=4k7
R53 "560112116006" CR1608-0603 55.2,46.025 r90 bottom value=4k7
R54 "560112116006" CR1608-0603 57.8,46.025 r90 bottom value=4k7
R55 "560112116006" CR1608-0603 60.3,46.025 r90 bottom value=4k7
R56 "560112116006" CR1608-0603 62.9,46.025 r90 bottom value=4k7
R57 "560112116006" CR1608-0603 65.4,46.025 r90 bottom value=4k7
R58 "560112116006" CR1608-0603 67.9,46.025 r90 bottom value=4k7
R59 "560112116006" CR1608-0603 70.4,46.025 r90 bottom value=4k7
R60 "560112116006" CR1608-0603 46.7,59.3 r0 bottom value=4k7
R61 "560112116005" CR1608-0603 41.1,59.2 r180 top value=10k
R62 "560112116006" CR1608-0603 41.9,61.4 r270 top value=4k7
R63 "560112116005" CR1608-0603 46.6,61.4 r90 top value=10k
R64 "560112116133" CR1608-0603 31.4,57.7 r270 top value=49R9
R65 "RC0603FR-075K1L" CR1608-0603 33,57.7 r270 top value=5k1
R66 "560112116005" CR1608-0603 32.2,53.8 r0 top value=10k
R67 "560112116005" CR1608-0603 32.2,55.3 r180 top value=10k
R68 "RC0603FR-075K1L" CR1608-0603 33,51.4 r90 top value=5k1
R69 "560112116133" CR1608-0603 31.4,51.4 r90 top value=49R9
R70 "560112116038" CR1608-0603 36.6,44.1 r0 top value=1k5
R71 "560112116038" CR1608-0603 36.6,42.6 r0 top value=1k5
R72 "560112116006" CR1608-0603 89.1,65.8 r90 top value=4k7
R73 "560112116005" CR1608-0603 76.1,70.1 r270 top value=10k
R74 "560112116091" CR1608-0603 89.1,70.2 r270 top value=2k
R75 "560112116009" CR1608-0603 77.7,70.1 r270 top value=100R
R76 "560112116014" CR1608-0603 84,65.8 r270 top value=1k
R77 "560112116133" CR1608-0603 123.8,58.7 r180 bottom value=49R9
R78 "560112116133" CR1608-0603 123.8,56.2 r180 bottom value=49R9
R79 "560112116133" CR1608-0603 123.8,51.6 r180 bottom value=49R9
R80 "560112116133" CR1608-0603 123.8,50 r180 bottom value=49R9
R81 "RC0603FR-070RL" CR1608-0603 123.8,54.7 r180 bottom value=0R
R82 "560112116005" CR1608-0603 100.3,67.7 r90 top value=10k
R83 "RC0603FR-0712K1L" CR1608-0603 112.2,55.1 r0 top value=12k1
R84 "560112116005" CR1608-0603 102.2,67.7 r270 top value=10k
R85 "560112116091" CR1608-0603 97.5,39.8 r0 top value=2k
R86 "560112116091" CR1608-0603 97.5,41.3 r0 top value=2k
R87 "560112116006" CR1608-0603 97.5,38.3 r180 top value=4k7
R88 "560112116005" CR1608-0603 98.3,67.7 r90 top value=10k
R89 "560112116005" CR1608-0603 107.1,46.1 r270 top value=10k
R90 "560112116020" CR1608-0603 118.7,57.2 r180 bottom value=330R
R91 "560112116020" CR1608-0603 118.7,48.8 r180 bottom value=330R
R92 "560112116020" CR1608-0603 115.7,46.1 r270 top value=330R
R93 "560112116020" CR1608-0603 111.3,46.1 r90 top value=330R
R94 "RC0603FR-070RL" CR1608-0603 84.3,61.1 r0 top value=0R
R95 "RC0603FR-070RL" CR1608-0603 84.3,59.3 r0 top value=0R
R96 "RC0603FR-070RL" CR1608-0603 84.3,57.5 r0 top value=0R
R97 "RC0603FR-070RL" CR1608-0603 84.3,55.7 r0 top value=0R
R98 "RC0603FR-070RL" CR1608-0603 84.3,52.1 r0 top value=0R
R99 "RC0603FR-070RL" CR1608-0603 84.3,53.9 r0 top value=0R
R100 "560112116005" CR1608-0603 79.1,61.1 r0 top value=10k
R101 "560112116005" CR1608-0603 79.1,59.3 r0 top value=10k
R102 "560112116005" CR1608-0603 79.1,57.5 r0 top value=10k
R103 "560112116005" CR1608-0603 79.1,55.7 r0 top value=10k
R104 "560112116005" CR1608-0603 79.1,52.1 r0 top value=10k
R105 "560112116005" CR1608-0603 79.1,53.9 r0 top value=10k
R106 "RC0603FR-070RL" CR1608-0603 82.6,61.1 r0 top value=0R
R107 "RC0603FR-070RL" CR1608-0603 82.6,59.3 r0 top value=0R
R108 "RC0603FR-070RL" CR1608-0603 82.6,57.5 r0 top value=0R
R109 "RC0603FR-070RL" CR1608-0603 82.6,55.7 r0 top value=0R
R110 "RC0603FR-070RL" CR1608-0603 82.6,52.1 r0 top value=0R
R111 "RC0603FR-070RL" CR1608-0603 82.6,53.9 r0 top value=0R
R112 "560112116034" CR1608-0603 96.2,65.8 r90 top value=33R
R113 "560112116034" CR1608-0603 94.4,65.8 r90 top value=33R
R114 "560112116034" CR1608-0603 92.7,50.2 r0 top value=33R
R115 "560112116034" CR1608-0603 89,58.9 r180 top value=33R
R116 "560112116034" CR1608-0603 89,50.2 r0 top value=33R
R117 "560112116034" CR1608-0603 92.7,58.9 r180 top value=33R
R118 "560112116034" CR1608-0603 92.7,52.6 r0 top value=33R
R119 "560112116034" CR1608-0603 89,53.9 r0 top value=33R
R120 "560112116034" CR1608-0603 92.6,65.8 r90 top value=33R
R121 "560112116034" CR1608-0603 89,52 r0 top value=33R
R122 "560112116034" CR1608-0603 98.3,46.1 r270 top value=33R
R123 "560112116034" CR1608-0603 99.9,46.1 r270 top value=33R
R124 "560112116034" CR1608-0603 92.7,55.1 r0 top value=33R
R125 "560112116034" CR1608-0603 99.9,46.1 r270 bottom value=33R
R126 "560112116034" CR1608-0603 89,57 r0 top value=33R
R127 "560112116034" CR1608-0603 98.3,46.1 r270 bottom value=33R
R128 "560112116034" CR1608-0603 92.7,57 r0 top value=33R
R129 "560112116034" CR1608-0603 96.7,46.1 r270 top value=33R
R130 "560112116034" CR1608-0603 92.7,61.1 r0 top value=33R
R131 "560112116034" CR1608-0603 89,61.1 r0 top value=33R
R132 "RC0603FR-070RL" CR1608-0603 84.3,47.4 r0 top value=0R
R133 "RC0603FR-070RL" CR1608-0603 84.3,45.6 r0 top value=0R
R134 "RC0603FR-070RL" CR1608-0603 84.3,43.8 r0 top value=0R
R135 "RC0603FR-070RL" CR1608-0603 84.3,42 r0 top value=0R
R136 "RC0603FR-070RL" CR1608-0603 84.3,38.4 r0 top value=0R
R137 "RC0603FR-070RL" CR1608-0603 84.3,40.2 r0 top value=0R
R138 "560112116005" CR1608-0603 79.1,47.4 r0 top value=10k
R139 "560112116005" CR1608-0603 79.1,45.6 r0 top value=10k
R140 "560112116005" CR1608-0603 79.1,43.8 r0 top value=10k
R141 "560112116005" CR1608-0603 79.1,42 r0 top value=10k
R142 "560112116005" CR1608-0603 79.1,38.4 r0 top value=10k
R143 "560112116005" CR1608-0603 79.1,40.2 r0 top value=10k
R144 "RC0603FR-070RL" CR1608-0603 82.6,47.4 r0 top value=0R
R145 "RC0603FR-070RL" CR1608-0603 82.6,45.6 r0 top value=0R
R146 "RC0603FR-070RL" CR1608-0603 82.6,43.8 r0 top value=0R
R147 "RC0603FR-070RL" CR1608-0603 82.6,42 r0 top value=0R
R148 "RC0603FR-070RL" CR1608-0603 82.6,38.4 r0 top value=0R
R149 "RC0603FR-070RL" CR1608-0603 82.6,40.2 r0 top value=0R
R150 "560112116038" CR1608-0603 92.9,38.9 r270 top value=1k5
R151 "560112116005" CR1608-0603 90.8,38.9 r90 top value=10k
R152 "560112116005" CR1608-0603 92.9,46.1 r270 top value=10k
R153 "RC0603FR-070RL" CR1608-0603 87.6,20.7 r180 bottom value=0R
R154 "560112116133" CR1608-0603 86,17.7 r180 top value=49R9
R155 "560112116133" CR1608-0603 86,20.7 r180 top value=49R9
R156 "560112116133" CR1608-0603 86,23.7 r180 top value=49R9
R157 "560112116133" CR1608-0603 86,26.7 r180 top value=49R9
R158 "RC0805FR-0775RL" CR2012-0805 101.3,17.5 r180 bottom value=75R
R159 "RC0805FR-0775RL" CR2012-0805 101.3,26.4 r180 bottom value=75R
R160 "CRCW12060000Z0EA" CR3216-1206 94.3,17.4 r180 bottom value=0R
R161 "CRCW12060000Z0EA" CR3216-1206 94.3,19.9 r180 bottom value=0R
R162 "CRCW12060000Z0EA" CR3216-1206 94.3,23.9 r180 bottom value=0R
R163 "CRCW12060000Z0EA" CR3216-1206 94.3,26.37 r180 bottom value=0R
R164 "RC0603FR-070RL" CR1608-0603 114.8,60.7 r0 top value=0R
S1 "418121270808" 418121270808 61.6,54.125 r0 top
S2 "434153017835" 434153017835 81.5,70.2 r180 top
Sign1 "ESD_380x350" ESD_380x351 18.1,59.7 r0 top
Sign2 "WEEE_275x400" WEEE_275x400 78.4,30.3 r180 bottom
Sign3 "CE_412x295" CE_412x295 18.6,62.2 r180 bottom
T1 "749070011" 749070011_WE-PoDL 22.2,44.07 r180 top
T2 "PSMN075-100MSEX" "LFPAK33 (SOT1210)" 59.8,27.7 r90 top
T3 "BSS123LT1G" SOT-23 50.7,32.9 r90 top value=BSS123
T4 "BSS138LT1G" SOT-23 86.6,66.1 r0 top
T5 "BSS123LT1G" SOT-23 50.8,13.1 r90 top value=BSS123
T6 "BUK9M120-100EX" "LFPAK33 (SOT1210)" 50.275,27.37 r180 top
T7 "BUK9M120-100EX" "LFPAK33 (SOT1210)" 50.67,16.871 r90 top
TP1 "PartNumber" "TESTPOINT 1.5mm" 109.2,33.005 r90 top value=1.5mm
TP2 "PartNumber" "TESTPOINT 1.5mm" 65.4,20.2 r90 top value=1.5mm
TP3 "PartNumber" "TESTPOINT 1.5mm" 44.9,62.9 r90 top value=1.5mm
TP4 "PartNumber" "TESTPOINT 1.5mm" 44.9,60.6 r90 top value=1.5mm
TP5 "PartNumber" "TESTPOINT 1.5mm" 104.3,67.9 r180 top value=1.5mm
TP6 "PartNumber" "TESTPOINT 1.5mm" 107.1,43.3 r90 top value=1.5mm
TP7 "PartNumber" "TESTPOINT 1.5mm" 92.9,41.3 r90 top value=1.5mm
TP8 "PartNumber" "TESTPOINT 1.5mm" 90.8,41.3 r90 top value=1.5mm
TP9 "PartNumber" "TESTPOINT 1.5mm" 90.8,45.3 r90 top value=1.5mm
TP10 "PartNumber" "TESTPOINT 1.5mm" 88,12.7 r90 top value=1.5mm
TP11 "PartNumber" "TESTPOINT 1.5mm" 88,6.9 r0 top value=1.5mm
VAR1 "82551600" CV3216-1206 11.7,50.7 r270 top
VAR2 "82551600" CV3216-1206 141.3,11.3 r90 top
X1 "632723300011" 632723300011_USB_TypeC 145,20.6 r90 top value="USB-C Receptacle"
X2 "09452812810" 09452812810 5.3,21.9 r270 top value="SPE PCB connector"
X3 "691322110003" 691322110003 8.2,40.5 r90 top value="Plug-in Terminal / 3P"
X4 "61300821121" HDR2X4 129,36.9 r0 top value="Male Header 2x4"
X6 "61300311121" HDR1X3 45.14,43.4 r180 top value="Male Header 1x3"
X7 "74990112116A" RJ45_74990112116A 135.1,54.3 r90 top locked
X8 "7490100110A" 7490100110A 94.375,21.9 r90 top
Y1 "830055299" CRYSTAL_3225 115.9,34.2 r180 top value=25MHz
Y2 "830055299" CRYSTAL_3225 36.3,61.4 r180 top value=25MHz
Y3 "830055299" CRYSTAL_3225 110.6,67.3 r180 top value=25MHz

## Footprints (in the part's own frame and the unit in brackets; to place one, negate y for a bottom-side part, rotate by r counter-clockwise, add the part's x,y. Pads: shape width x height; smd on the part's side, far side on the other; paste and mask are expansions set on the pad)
2038-xx [mm]
  rect 1.6x5.3 smd: 1(-3.3,0) 2(3.3,0) 3(0,0)
  silkscreen extent -2.3,-2.5 2.3,2.5, body extent -3.75,-2.5 3.75,2.5, height 5.3
749070011_WE-PoDL [mm]
  rect 0.7x1.5 smd: 1(-1.905,-4.25) 2(-0.635,-4.25) 3(0.635,-4.25) 4(1.905,-4.25) 5(1.905,4.25) 6(0.635,4.25) 7(-0.635,4.25) 8(-1.905,4.25)
  silkscreen extent -3.2,-4.2 3.05,3.25, body extent -3.25,-4.2 3.25,4.3, height 5.46
7490100110A [mm] "10/100 Base-T SMT  Transformer"
  rect 0.64x1.91 smd paste+0: 1(-4.445,-4.385) 2(-3.175,-4.385) 3(-1.905,-4.385) 4(-0.635,-4.385) 5(0.635,-4.385) 6(1.905,-4.385) 7(3.175,-4.385) 8(4.445,-4.385) 9(4.445,4.385) 10(3.175,4.385) 11(1.905,4.385) 12(0.635,4.385) 13(-0.635,4.385) 14(-1.905,4.385) 15(-3.175,4.385) 16(-4.445,4.385)
  silkscreen extent -6.35,-5.61 6.35,4.4, body extent -6.35,-4.7 6.35,4.7, height 6.35
09452812810 [mm] "SPE PCB connector"
  round 1.4 hole 0.9: 1(1.4,7.15) 2(-1.4,7.15)
  round 1.5 hole 1: SH(-4.45,0) SH(-3.8,9.75) SH(3.8,9.75) SH(4.45,0)
  silkscreen extent -4.75,-5.1 4.75,9.9, body extent -4.6,-5 4.6,9.9, height 5.87
418121270808 [mm] "DIP SWITCH"
  rect 1.1x2.2 smd: 1(-8.87,-4.4) 2(-6.33,-4.4) 3(-3.81,-4.4) 4(-1.27,-4.4) 5(1.27,-4.4) 6(3.79,-4.4) 7(6.33,-4.4) 8(8.87,-4.4) 9(8.87,4.4) 10(6.33,4.4) 11(3.79,4.4) 12(1.27,4.4) 13(-1.27,4.4) 14(-3.81,4.4) 15(-6.33,4.4) 16(-8.87,4.4)
  silkscreen extent -10.63,-3 10.63,3, body extent -10.63,-4.9 10.63,4.9, height 4.31
434153017835 [mm]
  rect 1.2x1 smd: 1(-1.7,0.8) 2(-1.7,-0.8) 3(1.7,0.8) 4(1.7,-0.8)
  silkscreen extent -1.75,-1.5 1.75,1.5, body extent -2.15,-1.45 2.15,1.45, height 1.7
632723300011_USB_TypeC [mm] "WR-COM USB 3.1 Horizontal"
  rect 0.3x1.2 smd paste+0 mask+0.064: A1(-2.75,10.58) A2(-2.25,10.58) A3(-1.75,10.58) A4(-1.25,10.58) A5(-0.75,10.58) A6(-0.25,10.58) A7(0.25,10.58) A8(0.75,10.58) A9(1.25,10.58) A10(1.75,10.58) A11(2.25,10.58) A12(2.75,10.58)
  round 0.65 hole 0.4 paste+0 mask+0.051: B1(2,9.33) B1(2.8,9.33) B2(2.4,8.63) B3(1.6,8.63) B4(1.2,9.33) B5(0.8,8.63) B6(0.4,9.33) B7(-0.4,9.33) B8(-0.8,8.63) B9(-1.2,9.33) B10(-1.6,8.63) B11(-2.4,8.63) B12(-2.8,9.33) B12(-2,9.33)
  oval 1x1.6 hole 0.6 slot 1.2 at 90 deg paste+0 mask+0.127: SH1(-4.27,3.45) SH2(-4.27,8.18) SH3(4.27,3.45)
  oval 1x1.5 hole 0.6 slot 1.2 at 90 deg paste+0 mask+0.127: SH4(4.27,8.18)
  silkscreen extent -4.4,-0.95 4.4,10.25, body extent -4.37,-0.95 4.37,10.84, height 3.03
691322110003 [mm]
  round 2.3 hole 1.4: 1(-3.5,0) 2(0,0) 3(3.5,0)
  silkscreen extent -5.95,-1.2 5.95,8, body extent -5.95,-1.2 5.95,8, height 7.25
CC1005-0402 [mm]
  rect 0.5x0.6 smd mask+0.1: 1(-0.5,0) 2(0.5,0)
  silkscreen extent -0.15,-0.24 0.15,0.24, body extent -0.5,-0.25 0.5,0.25, height 0.49
CC1608-0603 [mil]
  rect 34x33.46 smd: 1(-32.5,0) 2(32.5,0)
  silkscreen extent -6,-13 6,13, body extent -31,-16 31,16, height 31
CC2012-0805 [mm]
  rect 0.8x1.3 smd: 1(-0.9,0) 2(0.9,0)
  silkscreen extent -0.28,-0.58 0.27,0.57, body extent -1,-0.63 1,0.63, height 0.59
CC3216-1206 [mm]
  rect 1.6x1.8 smd: 1(-1.4,0) 2(1.4,0)
  silkscreen extent -0.4,-0.77 0.4,0.77, body extent -1.6,-0.8 1.6,0.8, height 0.77
CC3225-1210 [mm]
  rect 1.6x2.7 smd: 1(-1.4,0) 2(1.4,0)
  silkscreen extent -0.4,-1.25 0.4,1.25, body extent -1.6,-1.25 1.6,1.25, height 2.5
CE_412x295 [mm]
  silkscreen extent 0,0 10.46,7.44
CF2012-0805 [mm]
  rect 0.8x1.3 smd: 1(-0.9,0) 2(0.9,0)
  silkscreen extent -0.28,-0.58 0.27,0.57, body extent -1,-0.6 1,0.6, height 0.95
CR1608-0603 [mil]
  rect 34x33.46 smd: 1(-32.5,0) 2(32.5,0)
  silkscreen extent -6,-13 6,13, body extent -31,-16 31,16, height 18
CR2012-0805 [mm]
  rect 0.8x1.3 smd: 1(-0.9,0) 2(0.9,0)
  silkscreen extent -0.28,-0.58 0.28,0.58, body extent -1,-0.62 1,0.63, height 0.5
CR3216-1206 [mm]
  rect 1.3x1.8 smd: 1(-1.35,0) 2(1.35,0)
  silkscreen extent -0.4,-0.77 0.4,0.78, body extent -1.6,-0.8 1.6,0.8, height 0.55
CRYSTAL_3225 [mm] "CRYSTAL_3225"
  rect 1.3x1.05 smd: 1(-1.15,-0.925) 2(1.15,-0.925) 3(1.15,0.925) 4(-1.15,0.925)
  silkscreen extent -1.65,-1.97 1.65,1.3, body extent -1.6,-1.25 1.6,1.25, height 1.05
CV3216-1206 [mm]
  rect 1.6x1.8 smd: 1(-1.4,0) 2(1.4,0)
  silkscreen extent -0.4,-0.77 0.4,0.78, body extent -1.6,-0.8 1.6,0.8, height 1.5
"DFN1210-6L 1.2X1.0" [mm]
  rect 0.2x0.6 smd mask+0.051: 1(-0.4,-0.475) 2(0,-0.475) 3(0.4,-0.475) 4(0.4,0.475) 5(0,0.475) 6(-0.4,0.475)
  silkscreen extent -0.75,-1.05 0.75,0.75, body extent -0.6,-0.5 0.6,0.5, height 0.45
ESD_380x351 [mm]
  silkscreen extent 0,0 9.65,8.89
HDR1X3 [mm]
  rect 1.8x1.8 hole 0.9: 1(0,0)
  round 1.8 hole 0.9: 2(2.54,0) 3(5.08,0)
  silkscreen extent -1.27,-1.27 6.35,1.27, body extent -1.27,-1.27 6.35,1.27, height 8.54
HDR2X4 [mm]
  rect 1.5x1.5 hole 0.9: 1(-3.81,-1.27)
  round 1.5 hole 0.9: 2(-3.81,1.27) 3(-1.27,-1.27) 4(-1.27,1.27) 5(1.27,-1.27) 6(1.27,1.27) 7(3.81,-1.27) 8(3.81,1.27)
  silkscreen extent -5.08,-2.54 5.08,2.54, body extent -5.08,-2.54 5.08,2.54, height 8.57
INDUCTOR_WE-CNSW-1206 [mm] "Common Mode Choke"
  rect 1.1x0.6 smd: 1(-1.35,0.5) 2(1.35,0.5) 3(1.35,-0.5) 4(-1.35,-0.5)
  silkscreen extent -2.05,-0.9 2,0.9, body extent -1.6,-0.8 1.6,0.8, height 1.8
INDUCTOR_WE-CNSW-HF-0504 [mm] "Common Mode Choke"
  rect 0.45x0.45 smd: 1(-0.525,0.375) 2(0.525,0.375) 3(0.525,-0.375) 4(-0.525,-0.375)
  silkscreen extent -0.9,-0.72 0.9,0.73, body extent -0.6,-0.5 0.6,0.5, height 0.9
"Inductor_WE-DD 1280" [mm] "WE-DD SMT Shielded Coupled  Inductor"
  rect 2.5x3.85 smd: 1(1.75,5) 2(-1.75,5) 3(-1.75,-5) 4(1.75,-5)
  silkscreen extent -6.25,-6.25 6.25,6.25, body extent -6.25,-6.25 6.25,6.25, height 8.7
"Inductor_WE-LQS 3015" [mm] "WE-LQS SMT Power Inductor"
  rect 1x2.7 smd: 1(-1.2,0) 2(1.2,0)
  silkscreen extent -0.5,-1.5 0.5,1.5, body extent -1.5,-1.5 1.5,1.5, height 1.5
"Inductor_WE-LQS 6045" [mm] "WE-LQS SMT Power Inductor"
  rect 1.8x5.7 smd: 1(-2.3,0) 2(2.3,0)
  silkscreen extent -1.1,-3 1.1,3, body extent -3,-3 3,3, height 4.55
Inductor_WE-LQS-4018 [mm]
  rect 1.5x3.6 smd: 1(-1.75,0) 2(1.75,0)
  silkscreen extent -0.65,-2 0.65,2, body extent -2,-2 2,2, height 1.9
Inductor_WE-SL2 [mm] "WE-SL2 SMD Common Mode Line  Filter"
  rect 2.4x1.3 smd: 1(-3.95,-1.27) 2(-3.95,1.27) 3(3.95,1.27) 4(3.95,-1.27)
  silkscreen extent -3.15,-3.15 3.15,3.15, body extent -4.6,-3 4.6,3, height 5
"LED1608 (0603) - Green" [mm]
  rect 0.8x0.8 smd: 1(-0.75,0) 2(0.75,0)
  silkscreen extent -1.65,-0.67 1.4,0.67, body extent -0.81,-0.4 0.81,0.4, height 0.6
"LED1608 (0603) - Red" [mm]
  rect 0.8x0.8 smd: 1(-0.75,0) 2(0.75,0)
  silkscreen extent -1.65,-0.67 1.4,0.67, body extent -0.81,-0.4 0.81,0.4, height 0.6
"LED1608 (0603) - YELLOW" [mm]
  rect 0.8x0.8 smd: 1(-0.75,0) 2(0.75,0)
  silkscreen extent -1.65,-0.67 1.4,0.67, body extent -0.8,-0.4 0.8,0.4, height 0.6
"LED2012 (0805) - Green" [mm] "LED 0805"
  rect 1.1x1.3 smd: 1(-1.05,0) 2(1.05,0)
  silkscreen extent -2.1,-0.9 1.85,0.9, body extent -1.01,-0.63 1.01,0.63, height 1.1
"LFPAK33 (SOT1210)" [mm]
  rect 0.4x0.83 smd paste-0.05 mask+0.05: 1(-0.975,-1.93) 2(-0.325,-1.93) 3(0.325,-1.93) 4(0.975,-1.93)
  rect 0.4x0.75 smd paste-0.05 mask+0.05: mb(-0.975,1.18) mb(-0.325,1.18) mb(0.325,1.18) mb(0.975,1.18)
  rect 2.25x1.85 smd paste-5 mask+0.05: mb(0,0)
  body extent -1.64,-1.91 1.66,1.39, height 0.81
M3_VIA [mm]
  round 6 hole 3.2 mask+0.05: 0(0,0)
MAGI³C-VDRM_LGA-12EP [mm] "Variable Step Down LGA Module, SMT, body 10x6mm"
  rect 0.4x0.5 smd: 1(-4.65,-2.6) 2(-3.65,-2.6) 3(-2.65,-2.6) 4(-1.65,-2.6) 5(-0.65,-2.6) 8(-0.65,2.6) 9(-1.65,2.6) 10(-2.65,2.6) 11(-3.65,2.6) 12(-4.65,2.6)
  rect 1.5x1.5 smd: 6(4.1,-2.1) 7(4.1,2.1) 13(-3.05,0)
  silkscreen extent -5,-3.57 5,3, body extent -5,-3 5,3, height 3.02
"MSOP-12 PAD" [mil]
  rect 52.5x17 smd paste+0: 1(-87.25,63.98) 2(-87.25,38.39) 3(-87.25,12.8) 4(-87.25,-12.8) 5(-87.25,-38.39) 6(-87.25,-63.98) 7(87.25,-63.98) 8(87.25,-38.39) 9(87.25,-12.8) 10(87.25,12.8) 11(87.25,38.39) 12(87.25,63.98)
  rect 69x116 smd paste-57.5: EPAD(0,0)
  silkscreen extent -51,-81 51,83, body extent -99,-81 99,81, height 43
"QFN-40 6x6MM" [mm]
  rect 0.85x0.3 smd mask+0.076: 1(-2.95,2.25) 2(-2.95,1.75) 3(-2.95,1.25) 4(-2.95,0.75) 5(-2.95,0.25) 6(-2.95,-0.25) 7(-2.95,-0.75) 8(-2.95,-1.25) 9(-2.95,-1.75) 10(-2.95,-2.25) 21(2.95,-2.25) 22(2.95,-1.75) 23(2.95,-1.25) 24(2.95,-0.75) 25(2.95,-0.25) 26(2.95,0.25) 27(2.95,0.75) 28(2.95,1.25) 29(2.95,1.75) 30(2.95,2.25)
  rect 0.3x0.85 smd mask+0.076: 11(-2.25,-2.95) 12(-1.75,-2.95) 13(-1.25,-2.95) 14(-0.75,-2.95) 15(-0.25,-2.95) 16(0.25,-2.95) 17(0.75,-2.95) 18(1.25,-2.95) 19(1.75,-2.95) 20(2.25,-2.95) 31(2.25,2.95) 32(1.75,2.95) 33(1.25,2.95) 34(0.75,2.95) 35(0.25,2.95) 36(-0.25,2.95) 37(-0.75,2.95) 38(-1.25,2.95) 39(-1.75,2.95) 40(-2.25,2.95)
  rect 3.6x3.6 smd: 41(0,0)
  silkscreen extent -3.5,2.88 -3.25,3.13, body extent -3.05,-3.05 3.05,3.05, height 0.8
"QFN-48 7x7MM" [mm] "QFN, 48-Leads, Body 7x7mm (max), Pitch 0.50mm, IPC Medium Density"
  rect 0.7x0.25 smd mask+0.076: 1(-3.4,2.75) 2(-3.4,2.25) 3(-3.4,1.75) 4(-3.4,1.25) 5(-3.4,0.75) 6(-3.4,0.25) 7(-3.4,-0.25) 8(-3.4,-0.75) 9(-3.4,-1.25) 10(-3.4,-1.75) 11(-3.4,-2.25) 12(-3.4,-2.75) 25(3.4,-2.75) 26(3.4,-2.25) 27(3.4,-1.75) 28(3.4,-1.25) 29(3.4,-0.75) 30(3.4,-0.25) 31(3.4,0.25) 32(3.4,0.75) 33(3.4,1.25) 34(3.4,1.75) 35(3.4,2.25) 36(3.4,2.75)
  rect 0.25x0.7 smd mask+0.076: 13(-2.75,-3.4) 14(-2.25,-3.4) 15(-1.75,-3.4) 16(-1.25,-3.4) 17(-0.75,-3.4) 18(-0.25,-3.4) 19(0.25,-3.4) 20(0.75,-3.4) 21(1.25,-3.4) 22(1.75,-3.4) 23(2.25,-3.4) 24(2.75,-3.4) 37(2.75,3.4) 38(2.25,3.4) 39(1.75,3.4) 40(1.25,3.4) 41(0.75,3.4) 42(0.25,3.4) 43(-0.25,3.4) 44(-0.75,3.4) 45(-1.25,3.4) 46(-1.75,3.4) 47(-2.25,3.4) 48(-2.75,3.4)
  rect 5.2x5.2 smd mask+0.076: 49(0,0)
  silkscreen extent -4.12,-3.5 3.5,3.5, body extent -3.51,-3.51 3.51,3.51, height 0.78
"QFN-88 12X12MM" [mm]
  rect 0.65x0.3 smd: 1(-6.05,5.25) 2(-6.05,4.75) 3(-6.05,4.25) 4(-6.05,3.75) 5(-6.05,3.25) 6(-6.05,2.75) 7(-6.05,2.25) 8(-6.05,1.75) 9(-6.05,1.25) 10(-6.05,0.75) 11(-6.05,0.25) 12(-6.05,-0.25) 13(-6.05,-0.75) 14(-6.05,-1.25) 15(-6.05,-1.75) 16(-6.05,-2.25) 17(-6.05,-2.75) 18(-6.05,-3.25) 19(-6.05,-3.75) 20(-6.05,-4.25) 21(-6.05,-4.75) 22(-6.05,-5.25) 45(6.05,-5.25) 46(6.05,-4.75) 47(6.05,-4.25) 48(6.05,-3.75) 49(6.05,-3.25) 50(6.05,-2.75) 51(6.05,-2.25) 52(6.05,-1.75) 53(6.05,-1.25) 54(6.05,-0.75) 55(6.05,-0.25) 56(6.05,0.25) 57(6.05,0.75) 58(6.05,1.25) 59(6.05,1.75) 60(6.05,2.25) 61(6.05,2.75) 62(6.05,3.25) 63(6.05,3.75) 64(6.05,4.25) 65(6.05,4.75) 66(6.05,5.25)
  rect 0.3x0.65 smd: 23(-5.25,-6.05) 24(-4.75,-6.05) 25(-4.25,-6.05) 26(-3.75,-6.05) 27(-3.25,-6.05) 28(-2.75,-6.05) 29(-2.25,-6.05) 30(-1.75,-6.05) 31(-1.25,-6.05) 32(-0.75,-6.05) 33(-0.25,-6.05) 34(0.25,-6.05) 35(0.75,-6.05) 36(1.25,-6.05) 37(1.75,-6.05) 38(2.25,-6.05) 39(2.75,-6.05) 40(3.25,-6.05) 41(3.75,-6.05) 42(4.25,-6.05) 43(4.75,-6.05) 44(5.25,-6.05) 67(5.25,6.05) 68(4.75,6.05) 69(4.25,6.05) 70(3.75,6.05) 71(3.25,6.05) 72(2.75,6.05) 73(2.25,6.05) 74(1.75,6.05) 75(1.25,6.05) 76(0.75,6.05) 77(0.25,6.05) 78(-0.25,6.05) 79(-0.75,6.05) 80(-1.25,6.05) 81(-1.75,6.05) 82(-2.25,6.05) 83(-2.75,6.05) 84(-3.25,6.05) 85(-3.75,6.05) 86(-4.25,6.05) 87(-4.75,6.05) 88(-5.25,6.05)
  rect 6.1x6.1 smd: 89(0,0)
  silkscreen extent -6.5,5.88 -6.25,6.13, body extent -6.05,-6.05 6.05,6.05, height 1
RJ45_74990112116A [mm] "Ethernet Connectors WR-MJ Feml Shld Hztl 8P8C Tab Up LED&EMI"
  round 2.5 hole 1.6: B1(-7.9,3.05) B2(7.9,3.05)
  round 3.2 hole 3.25 unplated: H1(-5.715,0)
  round 3.25 hole 3.25 unplated: H2(5.715,0)
  rect 1.4x1.4 hole 0.9: P1(4.445,8.89)
  round 1.4 hole 0.9: P2(3.175,6.35) P3(1.905,8.89) P4(0.635,6.35) P5(-0.635,8.89) P6(-1.905,6.35) P7(-3.175,8.89) P8(-4.445,6.35)
  round 1.52 hole 1.02: P9(5.465,13.72) P10(2.925,13.72) P11(-2.925,13.72) P12(-5.465,13.72)
  silkscreen extent -9.99,-10.8 9.99,14.5, body extent -10.27,-10.8 10.27,14.5, height 15.78
SMA/DO-214AC [mm]
  rect 2.5x1.7 smd: 1(-2,0) 2(2,0)
  silkscreen extent -2.8,-1.5 2.8,1.5, body extent -2.65,-1.3 2.55,1.3, height 2.4
SMC/DO-214AB [mm]
  rect 2.5x3.3 smd: 1(-3.4,0) 2(3.4,0)
  silkscreen extent -4.1,-3.15 4.1,3.15, body extent -3.97,-2.95 3.98,2.95, height 2.3
"SMT 6.3mmx7.7mm - WE" [mm]
  rect 1.2x3 smd: 1(0,2.6) 2(0,-2.6)
  silkscreen extent -3.4,-3.4 3.4,3.4, body extent -3.3,-3.65 3.3,3.65, height 7.7
SO-8 [mm]
  rect 0.72x1.78 smd: 1(-1.905,-2.34) 2(-0.635,-2.34) 3(0.635,-2.34) 4(1.905,-2.34) 5(1.905,2.34) 6(0.635,2.34) 7(-0.635,2.34) 8(-1.905,2.34)
  silkscreen extent -2.73,-2.22 2.5,1.4, body extent -2.5,-3.17 2.5,3.17, height 1.88
SO-8N [mm]
  rect 0.6x2.2 smd: 1(-1.905,-2.6) 2(-0.635,-2.6) 3(0.635,-2.6) 4(1.905,-2.6) 5(1.905,2.6) 6(0.635,2.6) 7(-0.635,2.6) 8(-1.905,2.6)
  silkscreen extent -2.87,-2.46 2.5,1.1, body extent -2.5,-3.17 2.5,3.17, height 1.88
SOD-123FL [mm]
  rect 0.91x1.22 smd: 1(-1.64,0) 2(1.64,0)
  silkscreen extent -1.9,-0.9 1.95,0.9, body extent -1.85,-0.8 1.9,0.9, height 1.2
SOT-23 [mm]
  rect 0.85x1 smd: 1(-0.95,-1.2) 2(0.95,-1.2) 3(0,1.2)
  silkscreen extent -1.43,-0.3 1.43,1.2, body extent -1.46,-1.17 1.46,1.17, height 1
SOT-23-5 [mm] "TSOP-5, Case483-2"
  rect 0.7x1 smd: 1(-0.95,-1.2) 2(0,-1.2) 3(0.95,-1.2) 4(0.95,1.2) 5(-0.95,1.2)
  silkscreen extent -1.77,-1.57 1.53,0.88, body extent -1.46,-1.17 1.46,1.17, height 1
"TESTPOINT 1.5mm" [mm]
  round 1.5 smd paste+0: 1(0,0)
WE-TVS_824014885 [mm] "ESD Suppressors / TVS Diodes"
  rect 0.2x0.6 smd paste+0: 1(-1.7,-0.475) 2(-0.8,-0.475) 3(0,-0.475) 4(0.8,-0.475) 5(1.7,-0.475) 6(1.3,0.475) 7(0.4,0.475) 8(-0.4,0.475) 9(-1.3,0.475)
  silkscreen extent -1.9,-0.53 1.9,0.53, body extent -1.9,-0.5 1.9,0.5, height 0.5
WEEE_275x400 [mm]
  silkscreen extent -0.48,0 6.32,10.01
Wurth_994x400 [mm]
  silkscreen extent 0,-0.03 24.87,9.35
